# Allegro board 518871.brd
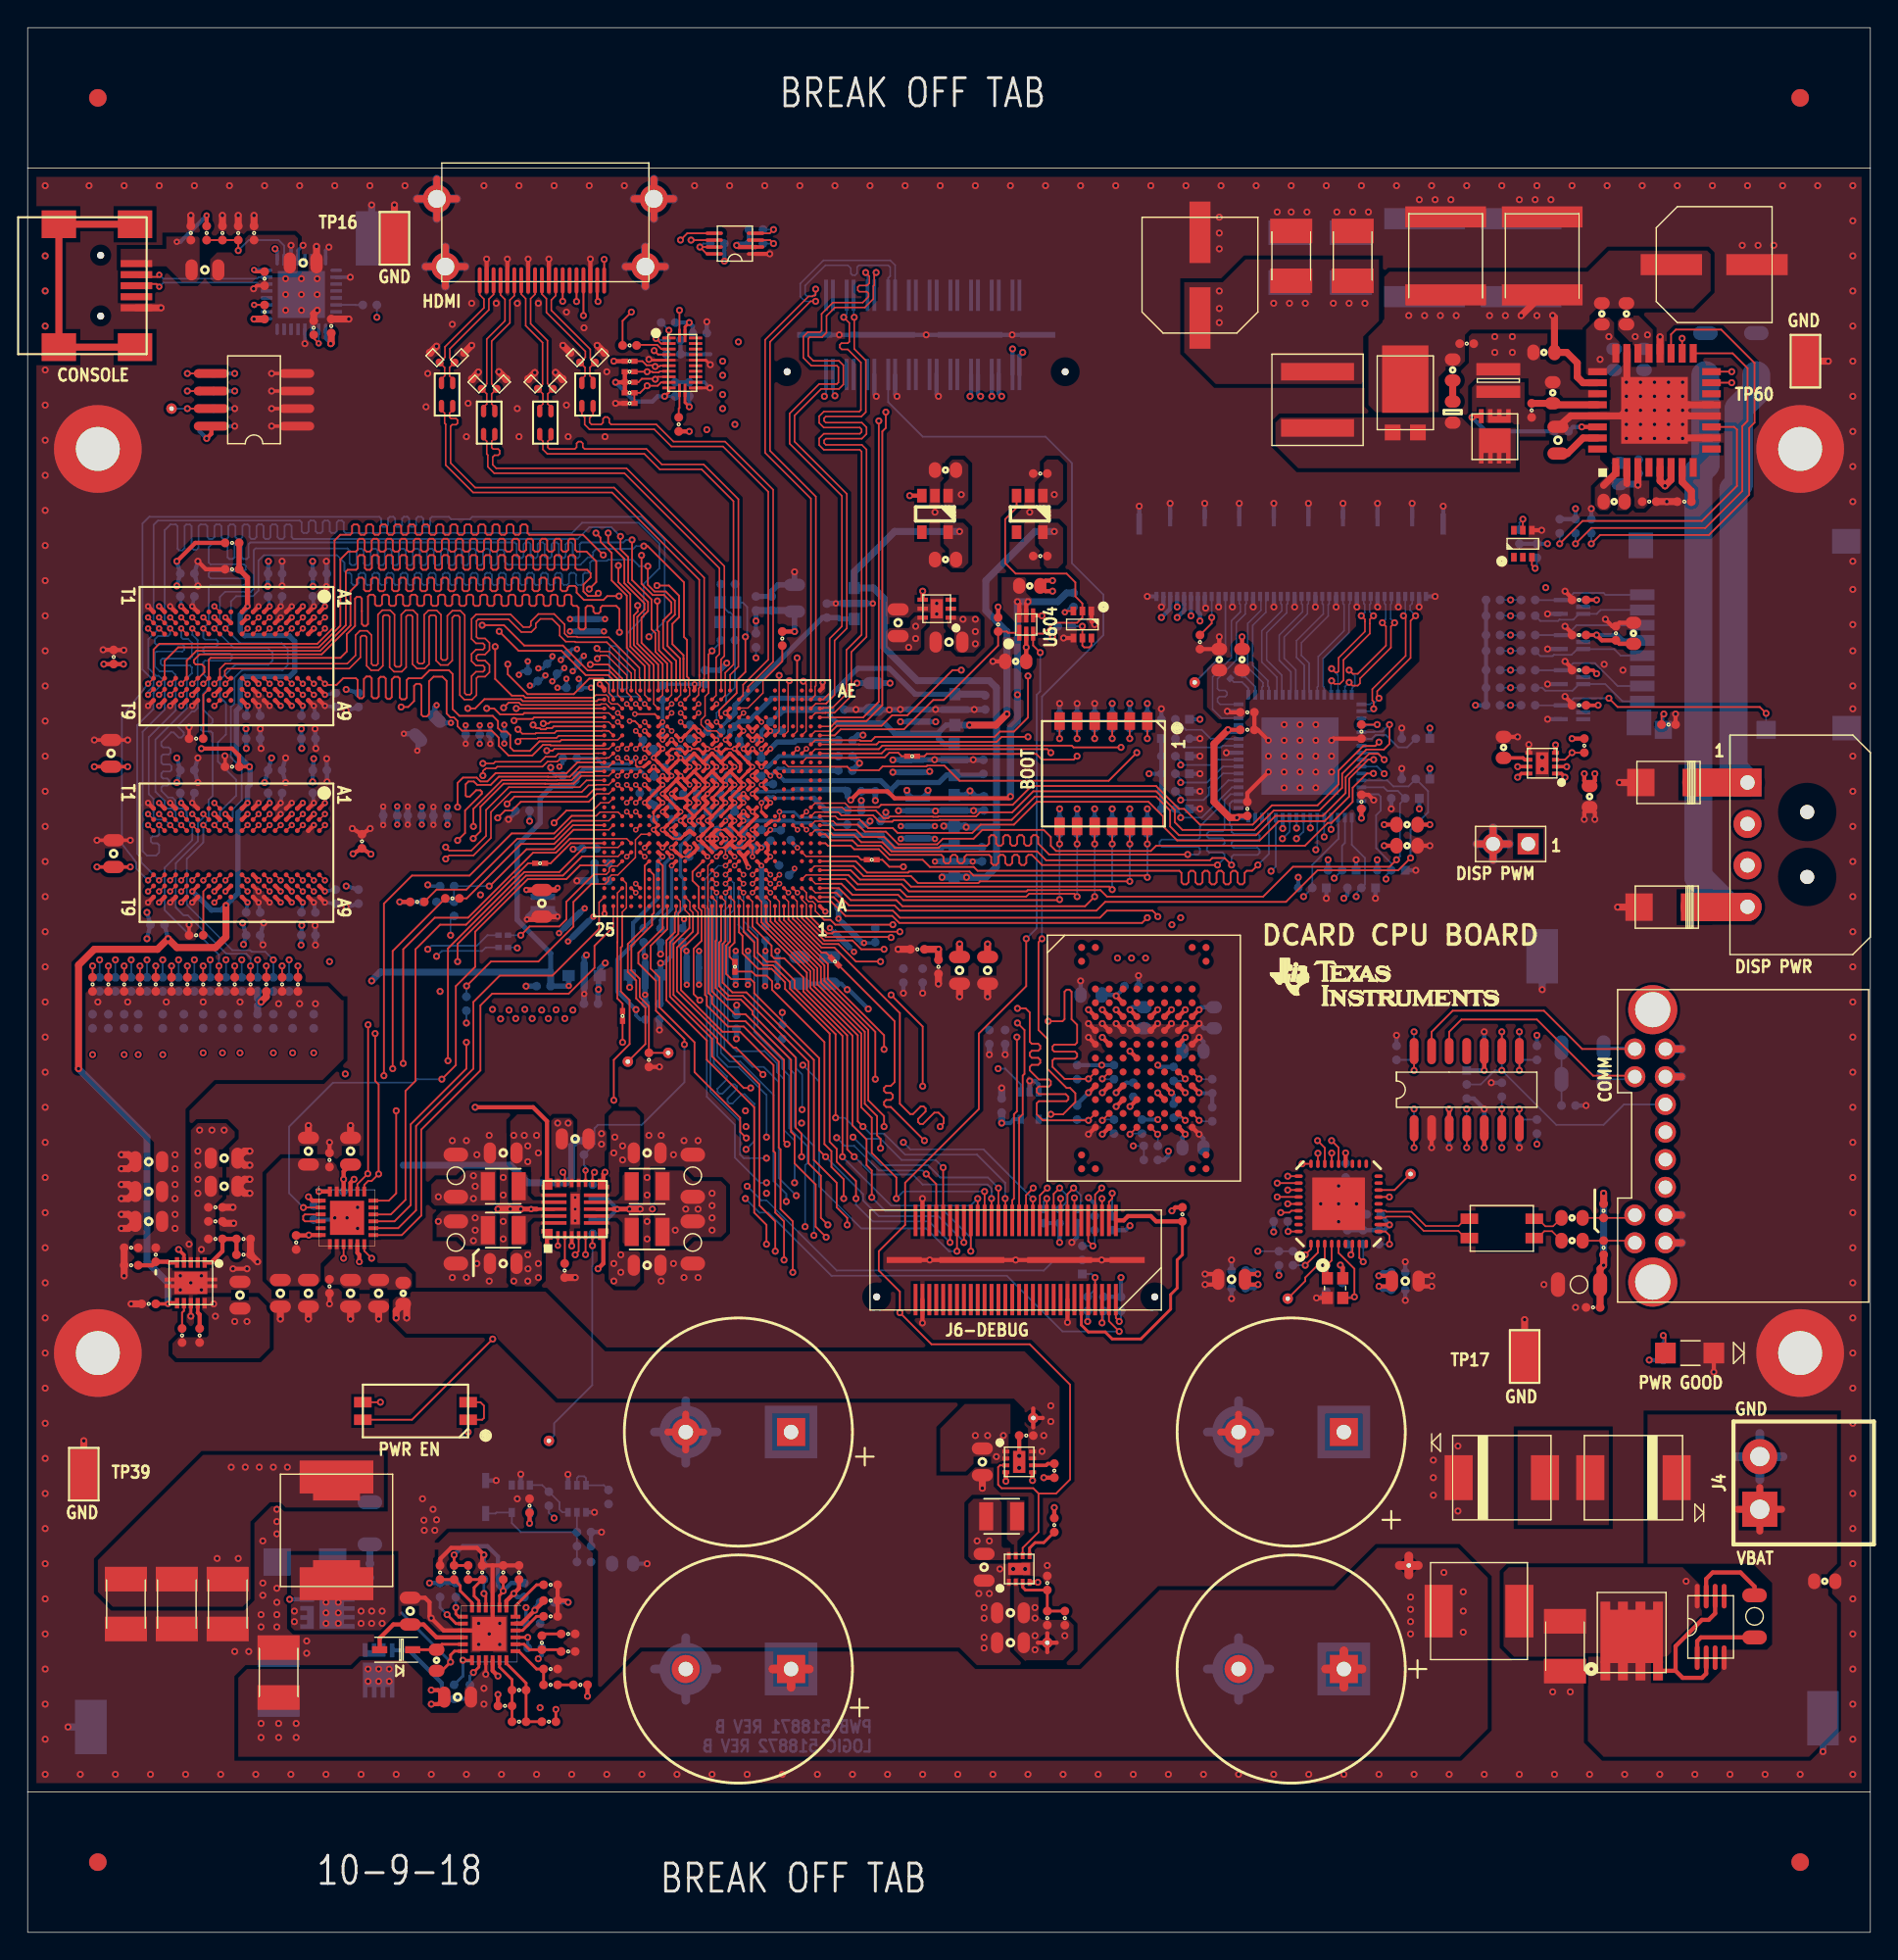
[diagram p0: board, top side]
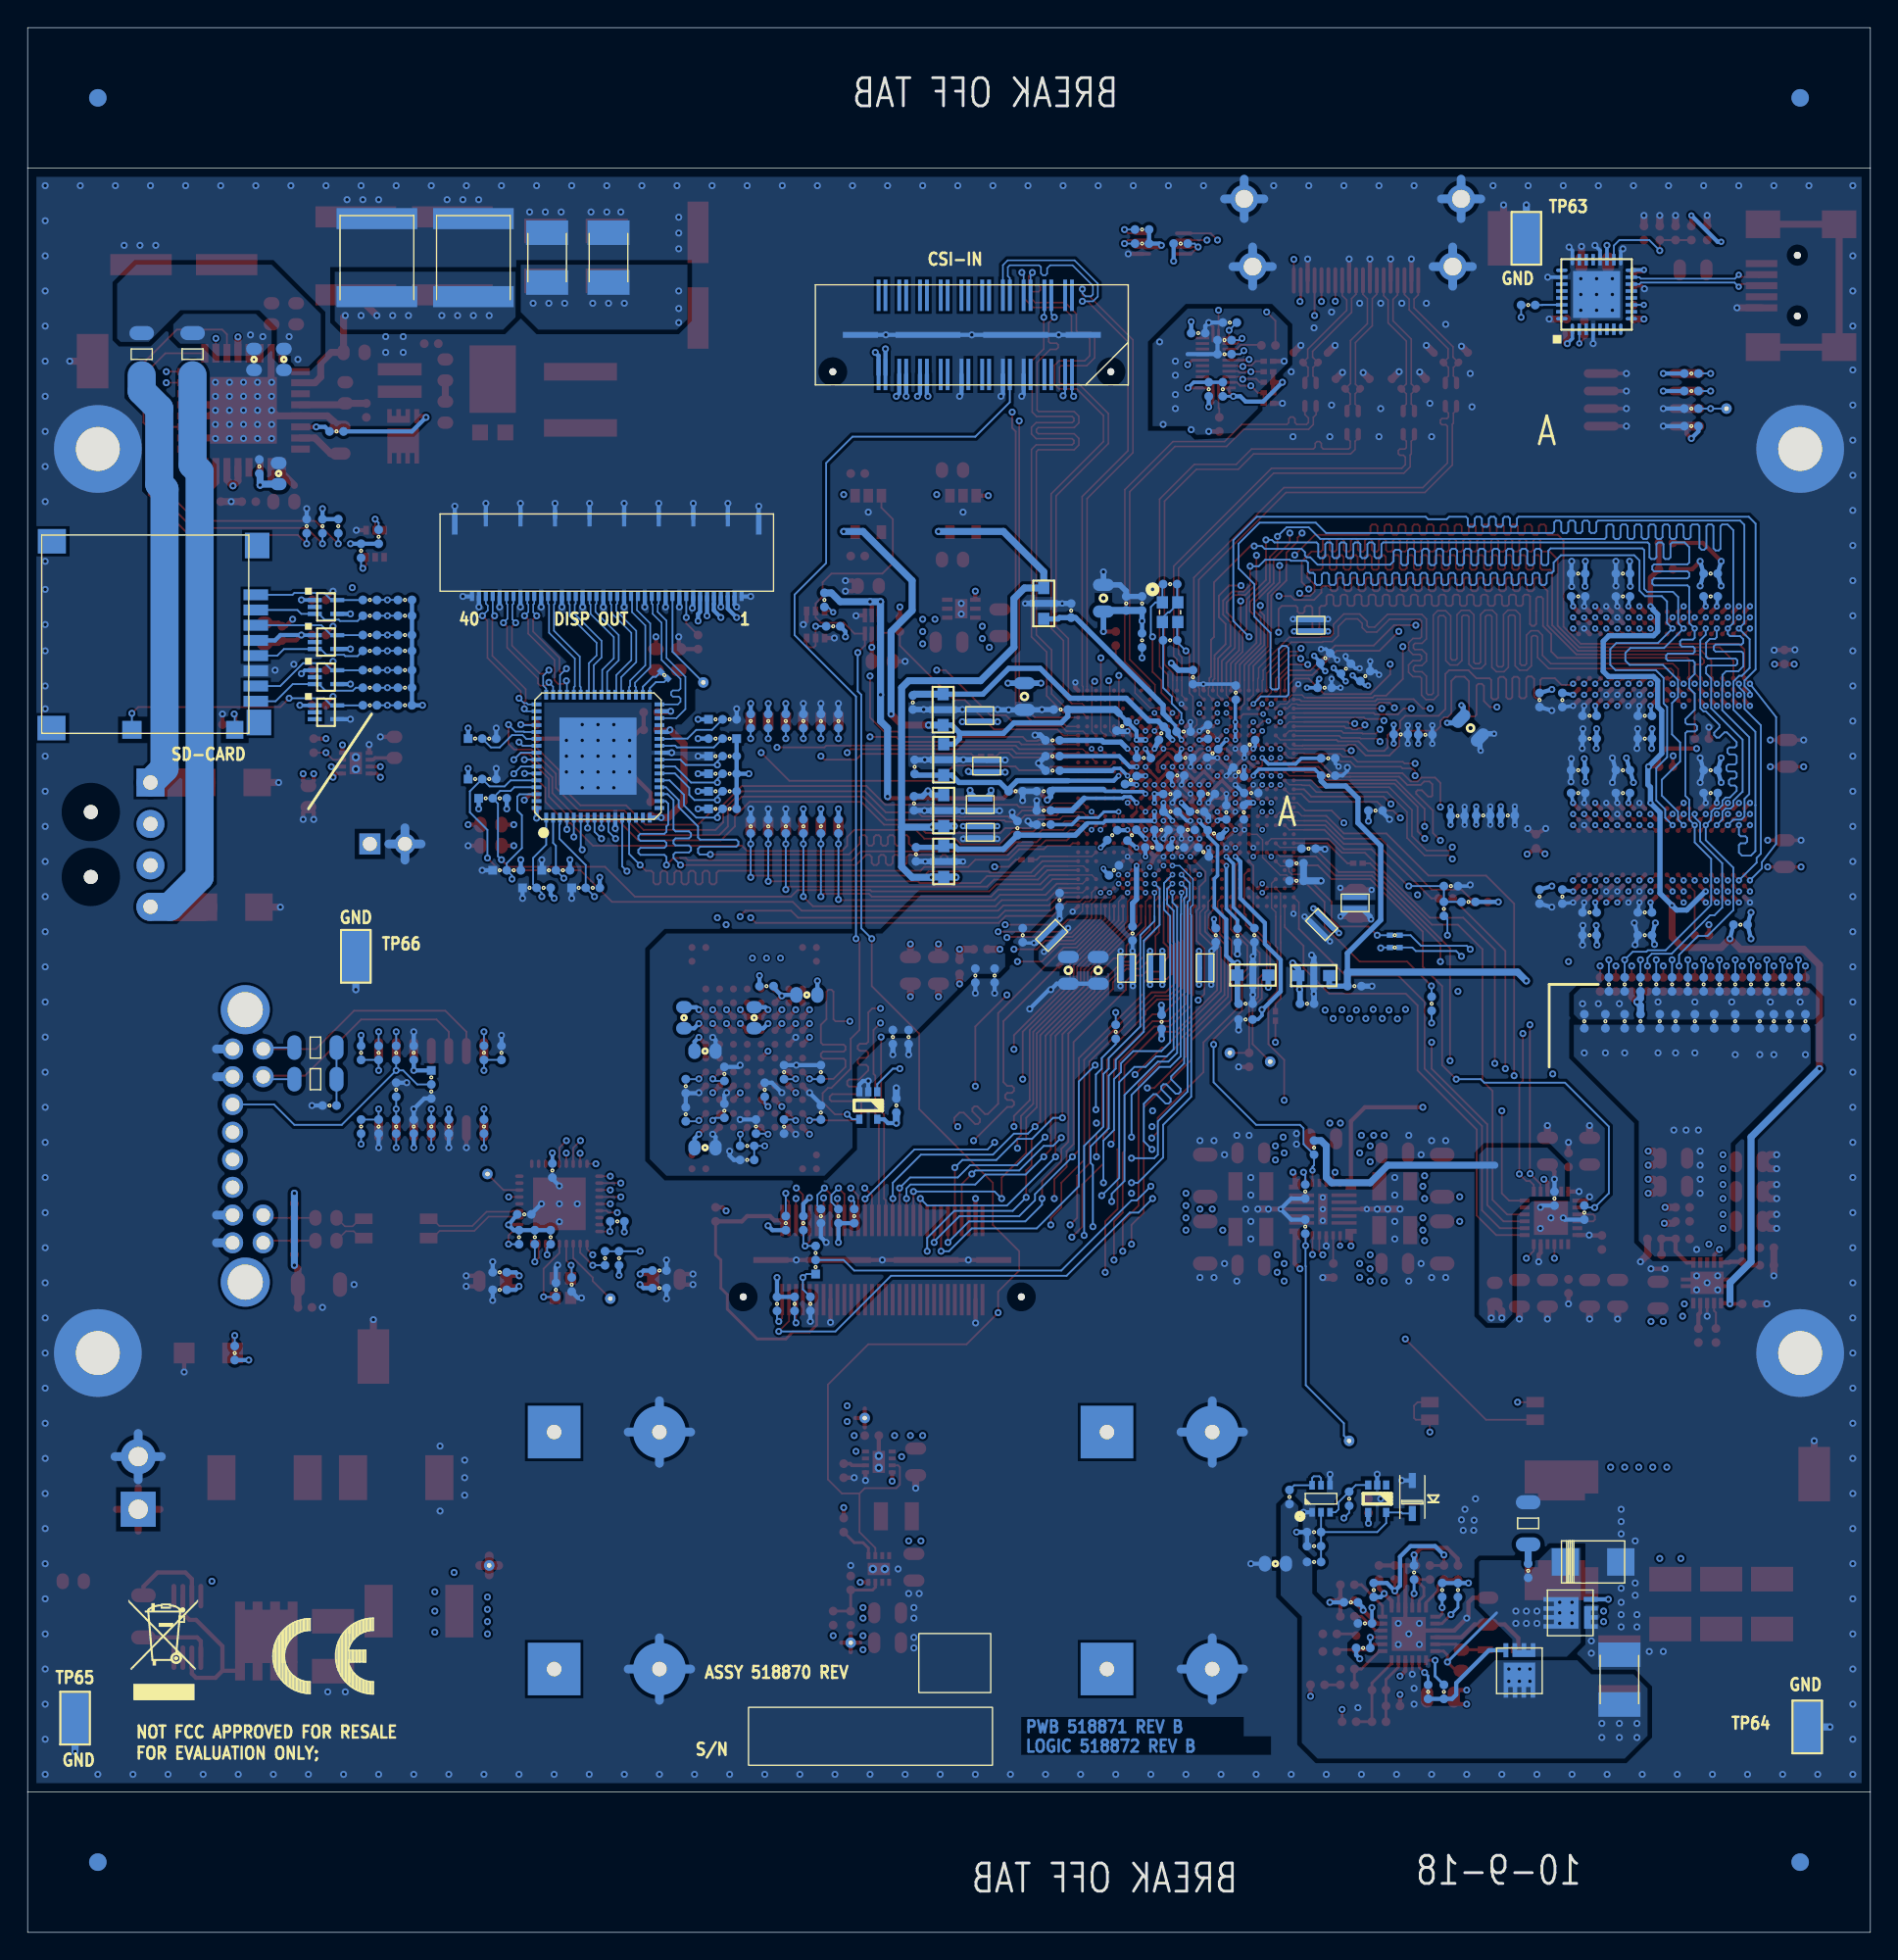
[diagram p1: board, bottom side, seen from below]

Outline 133.35 x 137.79 mm; copper layers: TOP, L2_GND, LY3, LY4, LY5_PWR, BOTTOM. Coordinates in mm from the lower left corner of the outline.
Outline path: 0,127.64 0,137.79 133.35,137.79 133.35,127.64 ; 0,127.64 133.35,127.64 ; 0,127.64 0,10.16 ; 133.35,127.64 133.35,10.16 ; 0,10.16 0,0 133.35,0 133.35,10.16 ; 0,10.16 133.35,10.16

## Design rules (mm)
net group CONN_USB_D: nets CONN_USB_D+ CONN_USB_D-
net group EMAC[1]_TXC: nets EMAC[1]_TXC N3026308320
net group H_MMC1_CLK: nets H_MMC1_CLK N27144522
net group HDMI_TX0+: nets H_HDMI_DY0 HDMI_TX0+
net group HDMI_TX0-: nets H_HDMI_DX0 HDMI_TX0-
net group HDMI_TX1+: nets H_HDMI_DY1 HDMI_TX1+
net group HDMI_TX1-: nets H_HDMI_DX1 HDMI_TX1-
net group HDMI_TX2+: nets H_HDMI_DY2 HDMI_TX2+
net group HDMI_TX2-: nets H_HDMI_DX2 HDMI_TX2-
net group HDMI_TXC+: nets H_HDMI_CLKY HDMI_TXC+
net group HDMI_TXC-: nets H_HDMI_CLKX HDMI_TXC-
net group VOUT3B_CLK: nets N33330487 VOUT3B_CLK
net group CAM: nets H_EMU5 H_EMU8 H_EMU9 H_EMU10 H_EMU11 H_EMU12 H_EMU13 H_EMU14 H_EMU15 H_EMU16 H_EMU17
net group CSI: nets H_CSI2_DX0 H_CSI2_DX1 H_CSI2_DX2 H_CSI2_DY0 H_CSI2_DY1 H_CSI2_DY2
net group DATA_GRP0: nets H_DDR1_D0 H_DDR1_D1 H_DDR1_D2 H_DDR1_D3 H_DDR1_D4 H_DDR1_D5 H_DDR1_D6 H_DDR1_D7 H_DDR1_DQM0 H_DDR1_DQS0_N H_DDR1_DQS0_P
net group DATA_GRP1: nets H_DDR1_D8 H_DDR1_D9 H_DDR1_D10 H_DDR1_D11 H_DDR1_D12 H_DDR1_D13 H_DDR1_D14 H_DDR1_D15 H_DDR1_DQM1 H_DDR1_DQS1_N H_DDR1_DQS1_P
net group DATA_GRP2: nets H_DDR1_D16 H_DDR1_D17 H_DDR1_D18 H_DDR1_D19 H_DDR1_D20 H_DDR1_D21 H_DDR1_D22 H_DDR1_D23 H_DDR1_DQM2 H_DDR1_DQS2_N H_DDR1_DQS2_P
net group DATA_GRP3: nets H_DDR1_D24 H_DDR1_D25 H_DDR1_D26 H_DDR1_D27 H_DDR1_D28 H_DDR1_D29 H_DDR1_D30 H_DDR1_D31 H_DDR1_DQM3 H_DDR1_DQS3_N H_DDR1_DQS3_P
net group EMAC[1]_RX: nets EMAC[1]_RXC EMAC[1]_RXCTL EMAC[1]_RXD0 EMAC[1]_RXD1 EMAC[1]_RXD2 EMAC[1]_RXD3
net group EMAC[1]_TX: nets EMAC[1]_TXCTL EMAC[1]_TXD0 EMAC[1]_TXD1 EMAC[1]_TXD2 EMAC[1]_TXD3
net group MMC2_CLK: nets MMC2_CLK N22073312 N32593135
net group PWR_PH: nets GND_EARTH VCAP_VBBLDO_DSP VCAP_VBBLDO_GPU VCAP_VBBLDO_IVA VCAP_VBBLDO_MPU VCAP_VDDRAM_CORE1 VCAP_VDDRAM_CORE3 VCAP_VDDRAM_CORE4 VCAP_VDDRAM_DSP VCAP_VDDRAM_GPU VCAP_VDDRAM_IVA VCAP_VDDRAM_MPU VCC_LM5141 VDA_HDMI_FIL1V8 VDA_MPU_ABE_FIL1V8 VDA_OSC_FIL1V8 VDDA_LM5141 VDDI_MMC2 VDDR_VREFSTL VHDMI_5V0 VTT_DDR
net group RX: nets RXEIN0+ RXEIN0- RXEIN1+ RXEIN1- RXEIN2+ RXEIN2- RXEIN3+ RXEIN3- RXOCLKIN+ RXOCLKIN- RXOIN0+ RXOIN0- RXOIN1+ RXOIN1- RXOIN2+ RXOIN2- RXOIN3+ RXOIN3-
net group TRD1_N: nets N30512862 TRD1_N TRD_N
net group TRD1_P: nets N30512853 TRD1_P TRD_P
net group VOUT3B: nets VOUT3B_D0 VOUT3B_D1 VOUT3B_D2 VOUT3B_D3 VOUT3B_D4 VOUT3B_D5 VOUT3B_D6 VOUT3B_D7 VOUT3B_D8 VOUT3B_D9 VOUT3B_D10 VOUT3B_D11 VOUT3B_D12 VOUT3B_D13 VOUT3B_D14 VOUT3B_D15 VOUT3B_D16 VOUT3B_D17 VOUT3B_D18 VOUT3B_D19 VOUT3B_D20 VOUT3B_D21 VOUT3B_D22 VOUT3B_D23 VOUT3B_DE VOUT3B_HSYNC VOUT3B_VSYNC

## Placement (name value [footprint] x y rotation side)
C1  NP-2200uF  [CAP300X630UP]  87.63 36.2 180 top
C2  NP-2200uF  [CAP300X630UP]  47.62 36.2 180 top
C3  NP-2200uF  [CAP300X630UP]  47.62 19.05 180 top
C8  10uF  [C1210-70X102]  111.25 20.7 270 top
C23  NP-2200uF  [CAP300X630UP]  87.63 19.05 180 top
C24  0.22uF  [C603-35X45]  130.05 25.4 0 top
C29  1uF  [C805-35X60]  31.11 17.02 180 top
C30  2.2uF 50V X7R  [C1206-40X70]  124.97 22.86 90 top
C36  0.1uF  [C402-25]  35.56 17.53 0 top
C37  10uF  [C1210-70X102]  18.16 18.29 90 bottom
C38  10uF  [C1210-70X102]  18.16 18.8 90 top
C39  0.1uF  [C603-35X45]  29.59 19.68 90 top
C40  150pF  [C402-25]  39.12 20.32 0 top
C41  0.015uF  [C402-25]  39.12 21.59 180 top
C43  0.047uF  [C402-25]  37.85 22.86 180 top
C45  4.7uF  [C805-35X60]  27.69 23.24 90 top
C48  0.01uF  [C402-25]  37.85 24 180 top
C51  0.01uF  [C402-25]  37.85 25.15 180 top
C53  0.1uF  [C402-25]  34.42 26.04 90 top
C54  0.01uF  [C402-25]  32.89 26.04 270 top
C56  22uF  [C1210-70X102]  14.48 23.75 270 top
C59  22uF  [C1210-70X102]  10.79 23.75 270 top
C64  22uF  [C1210-70X102]  7.11 23.75 270 top
C71  0.1uF  [C402-25RD]  11.81 122.94 90 top
C72  4700pF  [C402-25RD]  14.1 122.94 90 top
C73  0.1uF  [C402-25RD]  16.38 122.94 90 top
C78  4.7uF  [C805-35X60]  19.94 120.78 0 top
C80  0.47uF  [SM-7351-CAP-0402]  14.8 100.52 180 top
C81  0.1uF  [C402-25RD]  17.14 119.63 270 top
C82  0.47uF  [SM-7351-CAP-0402]  14.8 98.62 180 top
C83  0.1uF  [C402-25RD]  21.97 116.2 90 top
C84  0.47uF  [SM-7351-CAP-0402]  6.22 92.27 90 top
C89  10uF  [C805-35X60]  6.03 85.29 90 top
C91  0.47uF  [SM-7351-CAP-0402]  14.8 84.33 180 top
C96  0.47uF  [SM-7351-CAP-0402]  24.19 78.93 90 top
C98  10uF  [C805-35X60]  6.22 78.04 90 top
C108  10uF  [C805-35X60]  37.21 74.45 270 top
C114  0.47uF  [SM-7351-CAP-0402]  64.39 71.12 180 top
C118  1uF  [SM-7351-CAP-0402]  65.91 69.85 270 top
C119  4.7uF  [C805-35X60]  67.44 69.6 270 top
C120  10uF  [C805-35X60]  69.47 69.6 270 top
C122  4.7uF  [C603-35X45]  86.23 92.08 90 top
C129  4.7uF  [C603-35X45]  99.82 78.61 0 top
C143  10uF  [C805-35X60]  14.22 56.01 180 top
C144  10uF  [C805-35X60]  8.76 55.75 0 top
C153  10uF  [C805-35X60]  14.22 53.98 180 top
C154  10uF  [C805-35X60]  8.76 53.59 0 top
C155  0.1uF  [SM-7351-CAP-0402]  13.59 52.45 180 top
C156  10uF  [C805-35X60]  8.76 51.44 0 top
C157  1000pF  [C402-25]  13.59 51.44 180 top
C158  0.1uF  [SM-7351-CAP-0402]  7.49 49.53 0 top
C160  1000pF  [C402-25]  15.62 49.02 180 top
C161  10pF  [C402-25]  7.49 48.26 0 top
C163  10uF  [C805-35X60]  15.37 46.1 270 top
C164  0.1uF  [SM-7351-CAP-0402]  8.76 45.47 0 top
C189  10uF  [C805-35X60]  87.12 47.24 180 top
C194  10uF  [C805-35X60]  69.22 26.42 270 top
C203  10uF  [C805-35X60]  71.12 20.95 180 top
C204  10uF  [C805-35X60]  71.12 23.11 180 top
C212  10uF  [C805-35X60]  99.69 47.12 0 top
C220  100pF  [C402-25]  75.06 22.73 90 top
C232  0.1uF  [C603-35X45]  111.76 50.04 180 top
C233  0.1uF  [C603-35X45]  111.76 51.69 180 top
C267  0.1uF  [C402-25]  48.64 115.7 0 bottom
C268  0.1uF  [C402-25]  47.88 111.63 90 bottom
C269  0.1uF  [C402-25]  46.86 111.63 90 bottom
C270  1000pF  [C402-25]  24.77 26.16 270 bottom
C272  0.47uF  [SM-7351-CAP-0402]  21.15 98.3 0 bottom
C273  0.47uF  [SM-7351-CAP-0402]  17.91 98.3 0 bottom
C274  0.47uF  [SM-7351-CAP-0402]  11.56 98.3 0 bottom
C275  0.1uF  [C402-25]  12.95 108.97 180 bottom
C276  10pF  [C402-25]  50.67 97.54 180 bottom
C277  0.1uF  [SM-7351-CAP-0402]  41.53 76.07 180 bottom
C278  0.1uF  [SM-7351-CAP-0402]  21.15 96.65 180 bottom
C279  0.1uF  [SM-7351-CAP-0402]  17.91 96.65 0 bottom
C280  0.1uF  [SM-7351-CAP-0402]  11.56 96.65 0 bottom
C281  10uF  [C805-35X60]  55.5 96.52 90 bottom
C282  0.1uF  [SM-7351-CAP-0402]  35.81 81.15 180 bottom
C283  0.1uF  [SM-7351-CAP-0402]  54.86 79.38 315 bottom
C284  1uF  [SM-7351-CAP-0402]  53.85 96.14 90 bottom
C285  0.1uF  [SM-7351-CAP-0402]  52.7 96.14 90 bottom
C286  1uF  [SM-7351-CAP-0402]  57.84 95.62 90 bottom
C287  0.1uF  [SM-7351-CAP-0402]  41.53 77.34 180 bottom
C288  0.1uF  [SM-7351-CAP-0402]  54.74 76.83 315 bottom
C289  1uF  [SM-7351-CAP-0508]  40.49 94.56 90 bottom
C292  10pF  [C402-25]  50.67 93.47 0 bottom
C293  0.47uF  [SM-7351-CAP-0402]  39.45 92.18 135 bottom
C294  0.47uF  [SM-7351-CAP-0402]  37.95 91.41 135 bottom
C295  0.47uF  [SM-7351-CAP-0402]  36.55 90.88 135 bottom
C296  0.1uF  [SM-7351-CAP-0402]  49.02 90.81 270 bottom
C297  0.47uF  [SM-7351-CAP-0402]  39.5 90.04 180 bottom
C298  0.1uF  [SM-7351-CAP-0402]  45.92 89.69 90 bottom
C299  0.47uF  [SM-7351-CAP-0402]  23.94 89.15 270 bottom
C300  0.1uF  [SM-7351-CAP-0402]  22.29 89.15 270 bottom
C301  1uF  [SM-7351-CAP-0402]  69.29 88.98 270.1 bottom
C302  1uF  [SM-7351-CAP-0402]  58.59 88.46 0 bottom
C303  1uF  [SM-7351-CAP-0508]  64.46 88.03 90 bottom
C304  0.1uF  [SM-7351-CAP-0402]  20.32 88.01 0 bottom
C305  0.1uF  [SM-7351-CAP-0402]  16.32 88.01 0 bottom
C306  0.1uF  [SM-7351-CAP-0402]  54.15 87.26 321.4 bottom
C307  10uF  [C805-35X60]  28.93 87.12 225 bottom
C308  0.1uF  [SM-7351-CAP-0402]  47.93 86.85 90 bottom
C309  0.1uF  [SM-7351-CAP-0402]  49.7 86.87 180 bottom
C310  0.1uF  [SM-7351-CAP-0402]  51.31 86.74 290.4 bottom
C311  0.47uF  [SM-7351-CAP-0402]  33.99 86.66 180 bottom
C312  0.47uF  [SM-7351-CAP-0402]  32.21 86.64 180 bottom
C313  0.47uF  [SM-7351-CAP-0402]  20.32 86.36 0 bottom
C314  0.47uF  [SM-7351-CAP-0402]  16.32 86.36 0 bottom
C315  0.47uF  [SM-7351-CAP-0402]  44.91 85.93 320 bottom
C318  0.1uF  [SM-7351-CAP-0402]  52.58 84.96 181.1 bottom
C319  0.47uF  [SM-7351-CAP-0402]  47.6 85.29 322.7 bottom
C320  1uF  [SM-7351-CAP-0402]  59.18 86.23 360 bottom
C321  0.47uF  [SM-7351-CAP-0402]  49.58 84.96 180 bottom
C322  1uF  [SM-7351-CAP-0402]  39.24 84.94 180 bottom
C323  1uF  [SM-7351-CAP-0508]  63.95 84.37 90 bottom
C324  1uF  [SM-7351-CAP-0402]  69.16 84.32 90 bottom
C325  0.47uF  [SM-7351-CAP-0402]  45.72 83.95 40 bottom
C326  0.47uF  [SM-7351-CAP-0402]  21.15 84.07 0 bottom
C327  0.47uF  [SM-7351-CAP-0402]  17.91 84.07 0 bottom
C328  0.47uF  [SM-7351-CAP-0402]  11.56 84.07 0 bottom
C329  1uF  [SM-7351-CAP-0402]  59.17 84.05 0 bottom
C331  0.1uF  [SM-7351-CAP-0402]  39.23 83.68 180 bottom
C332  0.47uF  [SM-7351-CAP-0402]  50.16 83.69 180 bottom
C333  0.1uF  [SM-7351-CAP-0402]  61.85 82.55 180 bottom
C334  1uF  [SM-7351-CAP-0402]  59.82 81.16 0 bottom
C335  0.1uF  [SM-7351-CAP-0402]  44.81 82.42 0 bottom
C336  0.1uF  [SM-7351-CAP-0402]  21.15 82.42 180 bottom
C337  0.1uF  [SM-7351-CAP-0402]  17.91 82.42 0 bottom
C338  0.1uF  [SM-7351-CAP-0402]  11.56 82.42 0 bottom
C340  0.1uF  [SM-7351-CAP-0402]  50.66 82.35 180 bottom
C341  0.47uF  [SM-7351-CAP-0402]  47.94 82.36 180 bottom
C342  0.1uF  [SM-7351-CAP-0402]  53.52 83.36 145 bottom
C343  1uF  [SM-7351-CAP-0402]  69.2 81.68 270 bottom
C344  1uF  [SM-7351-CAP-0508]  64.42 81.59 270 bottom
C345  0.1uF  [SM-7351-CAP-0402]  59.82 82.55 0 bottom
C347  0.47uF  [SM-7351-CAP-0402]  50.65 81.08 180 bottom
C348  0.47uF  [SM-7351-CAP-0402]  48.72 81.08 180 bottom
C349  0.1uF  [SM-7351-CAP-0402]  46.61 81.03 90 bottom
C351  0.47uF  [SM-7351-CAP-0402]  28.02 80.8 180 bottom
C352  0.47uF  [SM-7351-CAP-0402]  26.24 80.8 180 bottom
C354  0.47uF  [SM-7351-CAP-0402]  29.87 80.77 180 bottom
C356  0.1uF  [SM-7351-CAP-0402]  45.34 81.03 90 bottom
C357  0.47uF  [SM-7351-CAP-0402]  53.44 79.38 309.4 bottom
C358  1uF  [SM-7351-CAP-0402]  59.82 80.14 0 bottom
C359  0.1uF  [SM-7351-CAP-0402]  61.72 79.88 90 bottom
C361  0.1uF  [SM-7351-CAP-0402]  49.4 79.76 180 bottom
C362  0.1uF  [SM-7351-CAP-0402]  51.31 79.76 0 bottom
C364  0.47uF  [SM-7351-CAP-0402]  47.5 79.5 206.5 bottom
C367  0.47uF  [SM-7351-CAP-0402]  50.16 78.49 0 bottom
C368  0.47uF  [SM-7351-CAP-0402]  48.26 78.16 220 bottom
C369  0.1uF  [SM-7351-CAP-0402]  40.65 78.4 180 bottom
C370  0.47uF  [SM-7351-CAP-0402]  51.97 78.49 180 bottom
C372  1uF  [SM-7351-CAP-0402]  69.06 77.99 270 bottom
C373  1uF  [SM-7351-CAP-0508]  64.41 79.59 270 bottom
C374  1uF  [SM-7351-CAP-0402]  44.58 72.14 270 bottom
C375  1000pF  [C402-25]  30.35 75.69 0 bottom
C377  0.47uF  [SM-7351-CAP-0402]  23.94 74.93 270 bottom
C378  0.1uF  [SM-7351-CAP-0402]  22.29 74.93 270 bottom
C379  0.1uF  [SM-7351-CAP-0402]  58.67 74.68 270 bottom
C380  1uF  [SM-7351-CAP-0508]  37.29 74.47 270 bottom
C382  0.1uF  [SM-7351-CAP-0402]  20.32 73.79 0 bottom
C383  0.1uF  [SM-7351-CAP-0402]  16.32 73.79 0 bottom
C385  1uF  [SM-7351-CAP-0508]  39.72 72.91 315 bottom
C386  0.47uF  [SM-7351-CAP-0402]  9.4 72.9 180 bottom
C388  1uF  [SM-7351-CAP-0402]  53.39 72.26 270 bottom
C390  0.1uF  [SM-7351-CAP-0402]  61.34 72.14 270 bottom
C391  0.47uF  [SM-7351-CAP-0402]  20.32 72.14 0 bottom
C392  0.47uF  [SM-7351-CAP-0402]  16.32 72.14 0 bottom
C393  1uF  [SM-7351-CAP-0508]  59.24 72.12 45 bottom
C394  1uF  [SM-7351-CAP-0402]  45.8 72.11 270 bottom
C395  1uF  [SM-7351-CAP-0402]  47.37 72.14 270 bottom
C401  1uF  [SM-7351-CAP-0508]  48.14 69.78 180 bottom
C402  1uF  [SM-7351-CAP-0508]  51.68 69.77 180 bottom
C403  1uF  [SM-7351-CAP-0508]  53.82 69.75 180 bottom
C406  1uF  [SM-7351-CAP-0402]  37.34 68.45 180 bottom
C407  1uF  [SM-7351-CAP-0402]  40.77 67.18 180 bottom
C408  1uF  [SM-7351-CAP-0402]  45.21 67.18 180 bottom
C409  0.1uF  [C402-25]  96.52 81.79 90 top
C410  0.1uF  [C402-25]  88.27 81.28 90 top
C411  0.22uF  [C603-35X45]  84.33 63.75 0 bottom
C412  1uF  [SM-7351-CAP-0402]  45.21 66.04 0 bottom
C413  0.47uF  [SM-7351-CAP-0402]  20.7 65.91 270 bottom
C414  0.47uF  [SM-7351-CAP-0402]  19.18 65.91 270 bottom
C415  0.47uF  [SM-7351-CAP-0402]  17.78 65.91 270 bottom
C416  0.1uF  [SM-7351-CAP-0402]  16.64 65.91 270 bottom
C417  0.47uF  [SM-7351-CAP-0402]  15.24 65.91 270 bottom
C418  0.47uF  [SM-7351-CAP-0402]  14.1 65.91 270 bottom
C419  0.47uF  [SM-7351-CAP-0402]  12.7 65.91 270 bottom
C420  0.47uF  [SM-7351-CAP-0402]  11.3 65.91 270 bottom
C421  0.47uF  [SM-7351-CAP-0402]  9.78 65.91 270 bottom
C422  0.47uF  [SM-7351-CAP-0402]  8 65.91 270 bottom
C423  0.47uF  [SM-7351-CAP-0402]  6.99 65.91 270 bottom
C424  0.47uF  [SM-7351-CAP-0402]  5.84 65.91 270 bottom
C425  0.47uF  [SM-7351-CAP-0402]  4.7 65.91 270 bottom
C426  1uF  [SM-7351-CAP-0402]  51.29 65.87 270 bottom
C427  2.2uF  [C603-35X45]  84.33 56.77 0 bottom
C428  0.47uF  [SM-7351-CAP-0402]  63.37 69.22 270 bottom
C429  0.1uF  [C402-25]  88.27 88.27 0 top
C430  0.1uF  [SM-7351-CAP-0402]  70.74 64.77 270 bottom
C431  0.1uF  [SM-7351-CAP-0402]  69.6 64.77 270 bottom
C432  0.1uF  [SM-7351-CAP-0402]  59.18 85.09 0 bottom
C433  0.1uF  [C402-25]  79.88 68.45 0 bottom
C434  1uF  [SM-7351-CAP-0402]  64.77 69.22 270 bottom
C435  4.7uF  [C603-35X45]  80.77 66.17 270 bottom
C436  2.2uF  [C603-35X45]  76.96 67.82 180 bottom
C437  0.22uF  [C603-35X45]  85.85 66.17 270 bottom
C442  0.1uF  [C402-25]  70.48 59.82 270 bottom
C503  10pF  [C402-25]  93.98 46.86 270 bottom
C506  10pF  [C402-25]  95.12 46.48 90 bottom
C507  100nF  [C402-25]  95.38 55.12 270 bottom
C508  1uF  [C402-25]  87.63 46.61 180 bottom
C509  10nF  [C402-25]  87.63 47.88 180 bottom
C511  100nF  [C402-25]  97.41 51.94 180 bottom
C514  0.1uF  [C402-25]  102.87 58.29 270 bottom
C518  1uF  [C402-25]  99.19 47.75 0 bottom
C519  10nF  [C402-25]  99.19 46.48 0 bottom
C521  0.1uF  [C402-25]  105.41 58.29 90 bottom
C525  4700pF  [C402-25]  111.51 59.82 0 bottom
C536  10uF  [C805-35X60]  58.04 69.6 270 bottom
C537  10uF  [C805-35X60]  55.88 69.6 270 bottom
C540  0.1uF  [C402-25]  114.94 93.98 90 top
C541  10uF  [C603-35X45]  116.2 93.98 90 top
C542  0.1uF  [C402-25]  112.27 96.39 180 top
C543  0.1uF  [C402-25]  112.27 88.77 180 top
C544  0.1uF  [C402-25]  112.27 91.31 180 top
C545  0.1uF  [C402-25]  112.27 93.85 180 top
C546  10uF  [C603-35X45]  113.03 82.17 270 top
C547  NP  [C603-35X45]  106.81 85.72 90 top
C551  10uF  [C805-35X60]  61.21 89.41 270 bottom
C552  0.22uF  [C603-35X45]  43.05 26.67 0 bottom
C553  150pF  [C402-25]  40.26 27.94 0 bottom
C554  NP-0.1uF  [C402-25]  36.32 30.86 270 top
C556  10uF  [C805-35X60]  23.37 56.52 90 top
C557  0.1uF  [C402-25]  22.86 53.09 270 bottom
C558  10uF  [C805-35X60]  20.32 56.52 90 top
C559  10uF  [C805-35X60]  18.29 46.23 270 top
C560  10uF  [C805-35X60]  20.32 46.23 270 top
C561  0.1uF  [C402-25]  21.84 55.88 90 top
C562  0.1uF  [C402-25]  21.84 46.74 270 top
C563  10uF  [C805-35X60]  25.4 46.23 270 top
C565  10uF  [C805-35X60]  23.37 46.23 270 top
C566  0.1uF  [C402-25]  105.41 63.63 90 bottom
C567  0.1uF  [C402-25]  19.43 49.91 90 top
C568  0.1uF  [C402-25]  88.27 87 0 top
C569  4.7nF  [C1206-40X70]  112.27 46.86 0 top
C600  4.7uF  [C805-35X60]  62.99 94.74 270 top
C601  22uF  [C1206-40X70]  30.99 54.74 90 top
C602  22uF  [C1206-40X70]  30.99 49.91 270 top
C603  4.7uF  [C805-35X60]  66.67 93.34 0 top
C604  0.1uF  [C402-25RD]  72.26 35.94 180 top
C605  10uF  [C805-35X60]  34.42 48.39 180 top
C606  10uF  [C805-35X60]  34.42 56.39 180 top
C607  4.7uF  [C805-35X60]  69.09 34.04 270 top
C608  NP-1000pF  [C402-25]  74.3 33.4 270 top
C609  2.2uF  [C603-35X45]  66.42 99.31 180 top
C610  10uF  [C805-35X60]  39.62 57.4 0 top
C611  2.2uF  [C603-35X45]  72.52 97.41 180 top
C612  10uF  [C805-35X60]  44.83 48.26 0 top
C613  10uF  [C805-35X60]  44.83 56.39 0 top
C614  2.2uF  [C603-35X45]  66.42 105.79 180 top
C615  22uF  [C1206-40X70]  48.13 49.91 270 top
C616  22uF  [C1206-40X70]  48.13 54.74 90 top
C617  2.2uF  [C603-35X45]  71.5 91.95 0 top
C618  0.1uF  [C402-25RD]  73.28 99.57 180 top
C619  1uF  [C402-25]  73.28 105.54 180 top
C620  10uF  [C1210-70X102]  91.44 121.28 90 top
C621  10uF  [C1210-70X102]  95.89 121.28 90 top
C622  10uF  [C1210-70X102]  95.76 121.16 90 bottom
C623  10uF  [C1210-70X102]  91.31 121.16 90 bottom
C624  33uF  [CAP-F-8383A]  84.84 119.89 180 top
C625  10uF  [C2220-60X230]  108.08 121.16 90 bottom
C626  10uF  [C2220-60X230]  101.09 121.16 90 bottom
C627  10uF  [C2220-60X230]  102.62 121.28 90 top
C628  10uF  [C2220-60X230]  109.6 121.28 90 top
C629  33uF  [CAP-F-8383A]  122.05 120.65 90 top
C630  1uF  [C603-35X45]  114.81 103.5 0 top
C631  1000pF  [C603-35X45]  110.36 111.38 270 top
C632  1uF  [C603-35X45]  115.19 105.54 270 bottom
C633  0.01uF  [C402-25]  117.35 103.5 180 top
C634  10uF  [C805-35X60]  110.74 107.95 270 top
C635  33pF  [C603-35X45]  109.73 114.3 0 top
C636  220pF  [C603-35X45]  103.12 113.03 270 top
C637  220pF  [C603-35X45]  113.92 117.09 270 top
C638  220pF  [C603-35X45]  114.81 113.79 90 bottom
C639  220pF  [C603-35X45]  115.7 117.09 270 top
C640  220pF  [C603-35X45]  116.97 113.79 90 bottom
C641  0.01uF  [C402-25]  116.59 106.05 270 bottom
C642  0.01uF  [C402-25]  104.14 114.94 180 top
D5  PMEG6010CEJ,115  [SOD323]  26.67 20.45 180 top
D21  SMCJ14A-13-F  [SMC-80X128]  106.68 32.89 0 top
D22  SMCJ30A-13-F  [SMC-80X128]  116.2 32.89 180 top
D23  B170-13-F  [SMA2-78SQ]  20.07 26.8 180 bottom
D24  NP-6.2V  [SOD323]  33.15 31.5 90 bottom
D25  PDS5100H-13-01  [DIODE-POWERDI5]  99.69 111.38 90 top
D26  SMAJ48A-13-F  [SMA2-78SQ]  118.75 83.19 180 top
D27  SMAJ48A-13-F  [SMA2-78SQ]  118.62 74.17 180 top
DS1  LED_GRN  [LED1206-59X59]  120.27 41.91 180 top
E1  80dB @ 27MHz  [EMI-NFM21P]  59.82 96.14 270 bottom
E2  80dB @ 27MHz  [EMI-NFM21P]  67.1 88.46 90 bottom
E3  80dB @ 27MHz  [EMI-NFM21P]  67.06 84.84 270 bottom
E4  80dB @ 27MHz  [EMI-NFM21P]  67.06 81.15 90 bottom
E5  80dB @ 27MHz  [EMI-NFM21P]  67.06 77.47 90 bottom
E6  80dB @ 27MHz  [EMI-NFM21P]  44.68 69.26 0 bottom
E7  80dB @ 27MHz  [EMI-NFM21P]  40.28 69.22 0 bottom
FL3  DLW21SN900HQ2  [EMI-36X15-DLW21-RDPADS]  30.35 111.25 90 top
FL4  DLW21SN900HQ2  [EMI-36X15-DLW21-RDPADS]  40.51 111.25 90 top
FL7  DLW21SN900HQ2  [EMI-36X15-DLW21-RDPADS]  33.4 109.22 90 top
FL8  DLW21SN900HQ2  [EMI-36X15-DLW21-RDPADS]  37.47 109.22 90 top
J1  NP  [JUMP1X2-6040]  108.58 78.74 270 top
J4  Phoenix - 1803277  [CON2R-150]  125.35 30.61 90 top
J7  USBMINI_AB  [SAMTEC-MUSB]  7.87 119.13 270 top
J14  MIPI-QSH-030  [QSH-030-01-F]  71.5 48.64 180 top
J17  Molex 34826-0124  [MOLEX-34826-0124]  117.6 56.9 90 top
J24  Molex_0436500400  [MOLEX4-043650]  124.46 83.19 90 top
J25  FH41-40S-0.5SH_5  [FH41-40S-SH]  91.44 99.69 0 bottom
L1  3.3uH, 5A  [IND2-7030D]  105.03 23.24 180 top
L6  2.2uH  [IND-IHLP-COMBO]  22.35 29.08 90 top
L9  BLM21PG221SN1  [L805-35X60]  12.83 120.27 0 top
L16  BLM18AG221SN1D  [L603-35X45]  99.82 80.14 0 top
L17  BLM18AG221SN1D  [L603-35X45]  87.88 92.08 90 top
L34  DFE252012PD-2R2M  [IND2520-40X80]  70.48 30.1 0 top
L44  AE2002  [CHOKE4-AE2002]  106.68 50.93 180 top
L45  BLM18AG221SN1D  [L603-35X45]  27.18 46.23 270 top
L600  0.47uH  [IND2520-40X80]  34.42 50.8 0 top
L601  0.47uH  [IND2520-40X80]  34.42 53.98 0 top
L602  0.47uH  [IND2520-40X80]  44.83 50.67 180 top
L603  0.47uH  [IND2520-40X80]  44.83 53.98 180 top
L604  22uH  [COIL-XAL60]  93.34 110.87 270 top
M1  -  [MHP125-250]  128.27 107.31 0 top
M2  -  [MHP125-250]  128.27 41.91 0 top
M3  -  [MHP125-250]  5.08 107.31 0 top
M4  -  [MHP125-250]  5.08 41.91 0 top
NOREF  -  [unnamed]  5.08 132.72 0 top
NOREF#2  -  [#2]  -332.71 -212.42 0 top
NOREF#3  -  [#2]  133.35 10.16 90 top
NOREF#4  -  [#2]  0 137.79 0 top
NOREF#5  -  [#2]  133.35 0 90 top
NOREF#6  -  [unnamed]  128.27 5.08 0 top
NOREF#7  -  [#2]  89.03 66.8 0 top
NOREF#8  -  [#2]  133.35 0 90 top
NOREF#9  -  [#2]  -332.71 -212.42 0 top
NOREF#10  -  [unnamed]  128.27 132.72 0 top
NOREF#11  -  [unnamed]  5.08 5.08 0 top
NOREF#12  -  [unnamed]  128.27 5.08 180 bottom
NOREF#13  -  [unnamed]  128.27 132.72 180 bottom
NOREF#14  -  [#2]  127 16.26 180 bottom
NOREF#15  -  [unnamed]  5.08 5.08 180 bottom
NOREF#16  -  [unnamed]  5.08 132.72 180 bottom
NOREF#17  -  [#2]  112.14 19.94 180 bottom
P1  HDMI-RA-19-TYPEA  [HDMI-SMT-W-FLANGE-RDPADS]  37.47 119.51 180 top
P9  QSH-020-01-L-D-DP-A  [QSH-020-DP-A]  65.02 115.57 0 bottom
P10  Micro SD, Reverse  [MOLEX-502774-0891]  124.21 93.98 270 bottom
Q3  SQJ422EP  [PWR-Q5A-SLPS319]  116.08 18.92 0 top
Q9  BSZ068N06NSATMA1  [TSDSON8]  25.4 18.92 0 bottom
Q10  BSZ068N06NSATMA1  [TSDSON8]  21.72 23.11 90 bottom
Q12  BSS138PS  [SOT363-16X45]  39.75 31.37 180 bottom
Q600  BSS138PS  [SOT363-16X45]  76.33 94.61 180 top
Q602  BSS138PS  [SOT363-16X45]  108.2 100.46 0 top
Q603  BSZ068N06NSATMA1  [TSDSON8]  106.17 108.2 180 top
R18  6.04k  [R402-25]  37.72 15.24 180 top
R22  0  [R402-25]  34.54 16.38 180 top
R23  200  [R402-25]  40.01 17.91 0 top
R24  34.8K  [R402-25]  37.85 17.91 0 top
R25  240  [R402-25]  43.56 114.81 0 top
R26  20K  [R402-25]  37.85 19.05 180 top
R27  NP  [R201-6P6SPC]  43.56 113.67 180 top
R28  NP  [R201-6P6SPC]  43.56 112.9 180 top
R29  3.01K  [R402-25]  37.21 20.95 270 top
R30  NP  [R201-6P6SPC]  43.56 112.14 180 top
R31  NP  [R201-6P6SPC]  43.56 111.38 0 top
R32  NP  [R201-6P6SPC]  43.56 110.62 180 top
R33  10K  [R402-25]  47.12 109.09 90 top
R34  0  [R402-25]  31.88 26.04 90 top
R35  NP  [R402-25]  30.86 26.04 90 top
R36  0  [R402-25]  29.84 26.04 270 top
R39  10K  [R402-25]  35.56 26.04 270 top
R51  4.7K  [R402-25]  12.95 122.94 90 top
R52  10K  [R402-25]  15.24 122.94 90 top
R55  10K  [R402-25]  17.14 117.22 90 top
R56  NP  [R402-25]  20.7 116.08 270 top
R64  240  [R402-25]  12.19 86.36 180 top
R66  100  [R201-6P6SPC]  64.01 85.09 180 top
R70  22  [R402-25]  30.73 74.8 180 top
R71  2.2K  [R402-25]  28.19 74.55 0 top
R75  0  [R201-6P6SPC]  37.08 77.34 180 top
R76  240  [R402-25]  12.19 72.14 180 top
R83  49.9  [SM-7351-RES-0402]  4.7 68.58 90 top
R84  49.9  [SM-7351-RES-0402]  5.84 68.58 90 top
R85  49.9  [SM-7351-RES-0402]  6.99 68.58 90 top
R86  49.9  [SM-7351-RES-0402]  8.13 68.58 90 top
R87  49.9  [SM-7351-RES-0402]  9.27 68.58 90 top
R88  49.9  [SM-7351-RES-0402]  10.41 68.58 90 top
R89  49.9  [SM-7351-RES-0402]  11.56 68.58 90 top
R90  49.9  [SM-7351-RES-0402]  12.7 68.58 90 top
R91  49.9  [SM-7351-RES-0402]  13.84 68.58 90 top
R92  49.9  [SM-7351-RES-0402]  14.99 68.58 90 top
R93  49.9  [SM-7351-RES-0402]  16.13 68.58 90 top
R94  49.9  [SM-7351-RES-0402]  17.27 68.58 90 top
R95  49.9  [SM-7351-RES-0402]  18.41 68.58 90 top
R96  49.9  [SM-7351-RES-0402]  19.56 68.58 90 top
R97  0  [R201-6P6SPC]  43.05 66.29 90 top
R99  0  [R201-6P6SPC]  58.42 70.23 135 top
R101  0  [R201-6P6SPC]  51.18 69.85 90 top
R104  2.2K  [R402-25]  44.96 63.12 90 top
R117  10K  [R402-25]  13.59 50.16 180 top
R118  10K  [R402-25]  15.62 50.16 180 top
R120  10  [R402-25]  9.27 49.02 90 top
R128  10K  [R402-25]  11.18 43.18 270 top
R129  100K  [R402-25]  12.45 43.18 270 top
R140  475K  [R402-25]  73.79 22.73 270 top
R141  150K  [R402-25]  73.79 25.27 270 top
R143  475K  [R402-25]  74.3 29.46 90 top
R152  62  [R1206-40X70]  112.52 61.72 0 bottom
R202  1K  [R402-25]  118.36 41.91 270 bottom
R212  NP  [R402-25]  46.35 116.46 0 bottom
R213  0  [R402-25]  30.86 17.4 90 bottom
R214  0  [R402-25]  32 17.4 270 bottom
R215  NP  [R402-25]  46.74 115.19 0 bottom
R216  10K  [R402-25]  46.74 114.17 180 bottom
R217  100K  [R402-25]  36.7 20.57 0 bottom
R218  10K  [R402-25]  36.58 22.35 0 bottom
R219  0  [R402-25]  29.84 24.77 270 bottom
R220  3.3  [R402-25]  30.99 24.77 90 bottom
R221  10K  [R402-25]  35.94 24.77 90 bottom
R222  42.2K  [R402-25]  33.02 26.04 270 bottom
R225  1.0  [R1206-40X70]  24.77 29.59 90 bottom
R226  NP  [R402-25]  106.05 92.71 0 bottom
R227  47K  [R402-25]  106.05 93.85 0 bottom
R228  47K  [R402-25]  106.05 91.31 0 bottom
R229  47K  [R402-25]  106.05 95.25 0 bottom
R230  47K  [R402-25]  106.05 90.04 0 bottom
R231  47K  [R402-25]  106.05 96.39 0 bottom
R232  22  [R402-25]  24.77 117.73 180 bottom
R233  3.32K  [R402-25]  12.95 112.78 0 bottom
R234  3.32K  [R402-25]  12.95 111.51 0 bottom
R235  10K  [R402-25]  12.95 110.24 0 bottom
R236  NP  [R402-25]  52.7 93.47 90 bottom
R240  1K  [R402-25]  74.68 87.63 270 bottom
R241  10K  [R402-25]  74.68 80.01 90 bottom
R243  10K  [R402-25]  75.95 80.01 90 bottom
R244  1K  [R402-25]  75.95 87.63 270 bottom
R245  2K  [R402-25]  52.7 122.17 0 bottom
R246  2K  [R402-25]  52.7 123.19 0 bottom
R247  10K  [R402-25]  77.22 80.01 90 bottom
R248  1K  [R402-25]  77.22 87.63 270 bottom
R249  4.7k  [R402-25]  49.91 122.17 180 bottom
R250  1K  [R402-25]  78.49 87.63 270 bottom
R251  10K  [R402-25]  78.49 80.01 90 bottom
R254  1K  [R402-25]  79.76 87.63 270 bottom
R255  10K  [R402-25]  79.76 80.01 90 bottom
R258  1K  [R402-25]  81.03 87.63 270 bottom
R259  10K  [R402-25]  81.03 80.01 90 bottom
R262  10K  [R402-25]  29.08 74.55 180 bottom
R263  100  [R402-25]  30.86 74.04 270 bottom
R264  22  [R402-25]  31.75 67.18 270 bottom
R265  0  [R201-6P6SPC]  34.42 72.14 0 bottom
R266  0  [R201-6P6SPC]  34.42 71.25 0 bottom
R268  47K  [R402-25]  85.72 61.21 90 bottom
R269  47K  [R402-25]  78.61 62.23 270 bottom
R270  47K  [R402-25]  85.72 59.18 270 bottom
R271  47K  [R402-25]  75.95 59.31 270 bottom
R272  47K  [R402-25]  82.93 62.1 270 bottom
R273  47K  [R402-25]  75.95 62.23 270 bottom
R276  49.9  [SM-7351-RES-0402]  18.92 68.58 90 bottom
R277  49.9  [SM-7351-RES-0402]  17.78 68.58 90 bottom
R278  49.9  [SM-7351-RES-0402]  16.64 68.58 90 bottom
R279  49.9  [SM-7351-RES-0402]  15.49 68.58 90 bottom
R280  49.9  [SM-7351-RES-0402]  14.35 68.58 90 bottom
R281  49.9  [SM-7351-RES-0402]  13.21 68.58 90 bottom
R282  49.9  [SM-7351-RES-0402]  12.06 68.58 90 bottom
R283  49.9  [SM-7351-RES-0402]  10.92 68.58 90 bottom
R284  49.9  [SM-7351-RES-0402]  9.78 68.58 90 bottom
R285  49.9  [SM-7351-RES-0402]  8.64 68.58 90 bottom
R286  49.9  [SM-7351-RES-0402]  7.49 68.58 90 bottom
R287  49.9  [SM-7351-RES-0402]  6.35 68.58 90 bottom
R288  49.9  [SM-7351-RES-0402]  5.21 68.58 90 bottom
R289  47K  [R402-25]  82.93 59.44 270 bottom
R291  47K  [R402-25]  78.61 58.29 90 bottom
R292  22  [R402-25]  54.61 65.15 270 bottom
R295  47K  [R402-25]  80.64 58.29 270 bottom
R296  1K  [R402-25]  80.01 60.96 90 bottom
R299  0  [R402-25]  81.28 56.9 0 bottom
R300  NP  [R402-25]  81.28 55.88 180 bottom
R307  4.7K  [R402-25]  78.49 51.31 90 bottom
R308  100  [R402-25]  83.57 51.94 270 top
R309  0  [R402-25]  75.95 51.82 90 bottom
R310  4.7K  [R402-25]  74.68 51.82 90 bottom
R311  4.7K  [R402-25]  73.53 51.82 90 bottom
R312  4.7K  [R402-25]  77.22 51.31 270 bottom
R328  4.7K  [R402-25]  79.12 45.47 270 bottom
R329  4.7K  [R402-25]  77.85 45.47 270 bottom
R330  4.7K  [R402-25]  76.71 45.47 270 bottom
R342  3.32K  [R402-25]  90.55 48.77 270 bottom
R344  1.5K  [R402-25]  90.68 51.44 0 bottom
R346  240  [R402-25]  91.57 48.77 270 bottom
R358  3.32K  [R402-25]  95.5 50.29 90 bottom
R360  3.32K  [R402-25]  96.65 50.29 90 bottom
R365  3.32K  [R402-25]  97.79 50.29 90 bottom
R371  100  [R402-25]  104.14 58.29 270 bottom
R372  100  [R402-25]  100.33 58.29 270 bottom
R382  3.32K  [R402-25]  109.22 63.63 270 bottom
R388  62  [R1206-40X70]  112.52 64.01 180 bottom
R401  NP  [R402-25]  37.59 23.88 0 bottom
R403  33  [R402-25]  108.58 96.39 0 bottom
R404  33  [R402-25]  108.58 95.25 0 bottom
R405  33  [R402-25]  108.58 93.85 0 bottom
R406  33  [R402-25]  108.58 92.71 0 bottom
R407  33  [R402-25]  108.58 91.31 0 bottom
R408  33  [R402-25]  108.58 90.04 0 bottom
R409  1K  [R402-25]  118.75 87.38 0 top
R410  10K  [R402-25]  106.05 88.77 0 bottom
R411  33  [R402-25]  108.58 88.77 0 bottom
R412  10K  [R402-25]  112.65 85.85 270 top
R426  100  [R402-25]  100.33 63.63 270 bottom
R428  2K  [R402-25]  35.56 15.24 180 top
R430  100K  [R402-25]  42.04 31.5 270 bottom
R431  274K  [R402-25]  40.26 26.8 0 bottom
R432  100K  [R402-25]  40.26 28.96 0 bottom
R433  0  [R402-25]  37.72 31.37 270 bottom
R435  33.2K  [R402-25]  106.68 63.63 270 bottom
R436  100  [R402-25]  109.22 58.29 90 bottom
R437  3.32K  [R402-25]  20.7 52.07 270 bottom
R438  100  [R402-25]  106.68 58.29 90 bottom
R439  100  [R402-25]  107.95 63.63 270 bottom
R440  10K  [R402-25]  106.68 60.96 270 bottom
R441  10K  [R402-25]  99.06 63.63 270 bottom
R443  10K  [R402-25]  96.52 86.87 270 top
R444  3.32K  [R402-25]  84.84 93.34 270 top
R445  0  [R201-6P6SPC]  61.09 77.6 180 top
R446  100K  [R402-25]  107.95 58.29 270 bottom
R447  NP  [R402-25]  54.61 93.6 90 top
R448  10K  [R402-25]  113.28 45.21 0 top
R449  1K  [R402-25]  114.05 52.2 90 top
R450  1K  [R402-25]  114.05 49.53 270 top
R600  28K  [R402-25]  38.86 47.88 270 top
R601  10K  [R402-25]  70.23 94.61 270 top
R602  10K  [R402-25]  40.26 56.77 270 bottom
R603  10K  [R402-25]  40.89 53.59 90 bottom
R604  NP-10K  [R402-25]  40.89 51.05 270 bottom
R605  100  [R402-25]  75.69 96.39 90 bottom
R606  10K  [R402-25]  75.06 94.49 180 bottom
R608  1K  [R402-25]  113.16 101.73 270 bottom
R609  10K  [R402-25]  110.87 101.73 270 bottom
R610  10K  [R402-25]  112.01 101.73 270 bottom
R611  10K  [R402-25]  107.95 100.97 90 bottom
R619  NP-2K  [R402-25]  109.22 99.95 270 bottom
R620  0  [R402-25]  111 108.58 0 bottom
R621  10  [R402-25]  108.84 110.11 270 top
R622  0.025  [R0612]  106.43 112.27 180 top
R623  24K  [R402-25]  119.89 103.5 0 top
R624  1  [R603-35X45]  103.12 109.98 270 top
R625  3.01 3/4W  [R1206-40X70]  125.09 114.17 90 bottom
R626  3.01 3/4W  [R1206-40X70]  121.41 114.17 90 bottom
R627  100  [R201-6P6SPC]  87.27 90.96 225 bottom
RJ16  10K.A  [JMP402-25]  100.2 82.04 180 bottom
RJ17  10K.A  [JMP402-25]  100.97 83.44 180 bottom
RJ18  10K.A  [JMP402-25]  83.57 81.28 180 bottom
RJ19  10K.A  [JMP402-25]  95.63 76.83 180 bottom
RJ20  10K.A  [JMP402-25]  99.19 76.83 180 bottom
RJ21  10K.A  [JMP402-25]  97.03 75.56 180 bottom
RJ22  10K.A  [JMP402-25]  93.47 75.56 180 bottom
RJ23  10K.A  [JMP402-25]  83.57 82.55 180 bottom
RJ24  10K.A  [JMP402-25]  83.57 85.09 180 bottom
RJ25  10K.A  [JMP402-25]  83.57 83.82 180 bottom
RJ26  0.A  [JMP402-25]  76.33 48.13 90 bottom
RJ27  3.32K.A  [JMP402-25]  104.14 61.85 270 bottom
RJ28  10K.A  [JMP402-25]  83.57 87.76 180 bottom
RJ29  10K.A  [JMP402-25]  100.97 86.36 180 bottom
RJ30  10K.A  [JMP402-25]  82.55 86.36 0 bottom
SW1  TDA06H0SB1R  [SW6-30X50-TDA]  77.85 83.82 180 top
SW2  SW DIP-2  [SW2-30X50-TDA]  28.07 37.72 90 top
TP1  TP  [TP-30RD13]  99.95 26.54 90 top
TP12  TP  [TP-30RD13]  37.72 35.56 270 top
TP16  SMT-TP  [TP1-70X135]  26.54 122.56 180 top
TP17  SMT-TP  [TP1-70X135]  108.33 41.66 0 top
TP18  TP  [TP-30RD13]  10.41 110.24 90 top
TP32  TP  [TP-30RD13]  43.43 62.99 0 top
TP36  TP  [TP-30RD13]  46.35 63.63 0 top
TP39  SMT-TP  [TP1-70X135]  4.06 33.15 0 top
TP40  TP  [TP-30RD13]  91.19 45.85 0 top
TP49  TP  [TP-30RD13]  100.08 54.86 270 top
TP51  TP  [TP-30RD13]  73.79 20.95 180 top
TP60  SMT-TP  [TP1-70X135]  128.65 113.67 0 top
TP63  SMT-TP  [TP1-70X135]  24.89 122.56 180 bottom
TP64  SMT-TP  [TP1-70X135]  4.57 14.86 180 bottom
TP65  SMT-TP  [TP1-70X135]  129.92 15.49 180 bottom
TP66  SMT-TP  [TP1-70X135]  109.6 70.61 180 bottom
TP67  TP  [TP-30RD13]  84.45 90.42 0 top
TP600  TP  [TP-30RD13]  72.77 37.21 180 top
U3  TPD1E05U06  [DPY-RDPADS]  29.46 113.92 135 top
U4  TPD1E05U06  [DPY-RDPADS]  31.24 113.92 45 top
U5  TPD1E05U06  [DPY-RDPADS]  39.62 113.92 135 top
U6  TPD1E05U06  [DPY-RDPADS]  41.4 113.92 45 top
U7  TPD1E05U06  [DPY-RDPADS]  32.51 112.01 135 top
U8  TPD1E05U06  [DPY-RDPADS]  34.29 112.01 45 top
U9  TPD1E05U06  [DPY-RDPADS]  36.58 112.01 135 top
U10  TPD1E05U06  [DPY-RDPADS]  38.35 112.01 45 top
U16  LM74610  [DGK8-14X70]  121.79 22.1 0 top
U17  TPD12S016RKTR  [RKT24]  47.37 113.54 270 top
U18  LM5141-Q1  [RGE24-11X28-4MM]  33.4 21.59 270 top
U22  24WC256  [SO8-25X75-295]  16.38 110.87 90 top
U23  MT41K512M16HA-125 AIT:A  [BGA6X16-P8-RE-PKG]  15.11 92.33 270 top
U26  PCA9306/PCA9306-Q1  [DCU8-10X50]  51.18 122.17 90 top
U27  X777AJGCBD  [J6ENTRY_DRA71X_ZDN_V4]  49.53 82.04 180 top
U29  MT41K512M16HA-125 AIT:A  [BGA6X16-P8-RE-PKG]  15.11 78.11 270 top
U31  MTFC32GAKAEDQ-AIT  [BGA100_1MM]  80.77 63.25 0 top
U35  TPS51200DRC  [DRC10-11X33]  11.81 46.99 180 top
U40  DP83TC811-Q1  [RND36-24X10]  94.87 52.7 0 top
U42  TPS61252  [DSG8-11X20]  71.75 26.29 0 top
U52  FT232RQ  [QFN32_5X5]  19.81 118.49 180 bottom
U54  SN74LVC1G125DCKR  [DCK-5]  72.52 59.82 0 bottom
U66  TPD2E001DRL-Q1  [DRL5-12X40]  111.76 90.81 270 bottom
U67  TPD2E001DRL-Q1  [DRL5-12X40]  111.76 93.34 270 bottom
U68  TPD2E001DRL-Q1  [DRL5-12X40]  111.76 95.89 270 bottom
U69  TPD2E001DRL-Q1  [DRL5-12X40]  111.76 88.27 270 bottom
U70  TPS22965DSG  [DSG8-11X20]  109.6 84.58 90 top
U76  NP-TPS3803-01-Q1  [DCK-5]  35.69 31.37 0 bottom
U77  DS90C189-Q1  [RTD64]  92.08 85.09 90 bottom
U78  TAS2505IR  [RGE24-11X28-4MM]  23.11 51.69 0 top
U79  TCAN1043D-Q1  [SO14-25X75]  104.14 60.96 0 top
U600  LP5912Q1.8DRVTQ1  [DRV6-12X30]  65.79 95.76 90 top
U601  TPS22965-Q1DSG  [DSG8-11X20]  71.75 34.04 270 top
U602  LP87523-Q1  [VQFNHR26]  39.62 52.32 90 top
U603  LP5907QMFX-1.8Q1  [DBV5-27X39]  65.66 102.62 180 top
U604  TLV7103318-Q1  [DSE6]  72.26 94.61 0 top
U605  TLV71318PQDBVRQ1  [DBV5-27X39]  72.52 102.62 180 top
U606  LP8860-Q1  [VFP0032B]  117.73 110.11 90 top
Y2  25MHz/10pF  [XTAL4-ABM11]  94.61 46.61 270 top
Y3  19.2MHz/10pF  [XTAL4-ABM11]  50.67 95.5 270 bottom

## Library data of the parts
C1-C3 C23 C624 C629 = CAP
C8 C24 C122 C129 C189 C212 C427 C435 C436 C541 C546 C547 C552 C556 C558-C560 C563 C565 C569 = CAP: Tolerance: X; User Part Number: X
C29 C30 C37 C38 C620-C623 C630 C632 C634 = CAP NP_0: Tolerance: X; User Part Number: X
C36 C43 C53 C554 = CAP NP_2: User Part Number: USERPART#; Tolerance: TOLERANCE
C39 C143 C144 C153 C154 C156 C163 C631 C635-C640 = CAP NP: Tolerance: X; User Part Number: X
C40 C276 C292 C375 C503 C506 C553 = CAP NP_3: User Part Number: USERPART#; Tolerance: TOLERANCE
C41 C48 C51 C54 C71 C73 C81 C83 C157 C160 C161 C267-C270 C442 C633 C641 C642 = CAP NP: User Part Number: USERPART#; Tolerance: TOLERANCE
C45 C78 = CAP NP_2: Tolerance: X; User Part Number: X
C56 C59 C64 = CAP NP_0: Tolerance: 20%; User Part Number: X; tolerance: 20%
C72 C220 C409 C410 C429 C507-C509 C511 C514 C518 C519 C521 C525 C566 C568 = CAP: User Part Number: USERPART#; Tolerance: TOLERANCE
C80 C82 C84 C91 C96 C272-C274 C293-C295 C297 C299 C311-C315 C319 C321 C325-C328 C332 C341 C347 C348 C351 C352 C354 C357 C361 C362 C364 C367 C368 C377 C386 C391 C392 C413-C415 C417-C425 = CAP_AM_0402_0.47uf_x7s_10v_20_X: Tolerance: +/-10%; User Part Number: USERPART#; tolerance: +/-10%
C89 C98 C108 C120 C194 C203 C204 C281 C307 C536 C537 C551 C605 C606 C610 C612 C613 = CAP_AM_0805_10uf_x7r_10v_10_X: Tolerance: X; User Part Number: X
C114 C370 C428 = CAP_AM_0402_0.47uf_x7s_10v_20_X: User Part Number: USERPART#; Tolerance: +/-10%; tolerance: +/-10%
C118 C284 C434 = CAP_AM_0402_1uF_X7S_10V_10%_X: User Part Number: USERPART#; Tolerance: 10%; tolerance: 10%
C119 C600 C603 = CAP_AM_0805_4.7uf_x7r_16v_10_X: Tolerance: X; User Part Number: X
C155 C158 C164 = CAP NP: Tolerance: TOLERANCE; User Part Number: USERPART#
C232 C233 = CAP NP: Tolerance: X; User Part Number: X; signal model: CAP_NP_C603-35X45_0.1UF
C275 = CAP .1 uF 10% 0603: User Part Number: USERPART#; Tolerance: TOLERANCE
C277 C282 C283 C285 C287 C288 C296 C342 C379 C390 C430-C432 = CAP_AM_0402_0.1uf_x7r_16v_10%_X: User Part Number: USERPART#; Tolerance: TOLERANCE
C278-C280 C298 C300 C304-C306 C308-C310 C318 C331 C333 C335-C338 C340 C345 C349 C356 C359 C369 C378 C382 C383 C416 = CAP_AM_0402_0.1uf_x7r_16v_10%_X: Tolerance: TOLERANCE; User Part Number: USERPART#
C286 C301 C302 C320 C322 C324 C329 C334 C343 C358 C372 C374 C388 C394 C395 C406-C408 C412 C426 = CAP_AM_0402_1uF_X7S_10V_10%_X: Tolerance: 10%; User Part Number: USERPART#; tolerance: 10%
C289 C303 C323 C344 C373 C380 C385 C393 C401-C403 = CAP_AM_0508_1uF_X7S_4V_20%_X: tolerance: 20%
C411 C437 = Cap 100nF Cermc 16V 10% 603_4: Tolerance: X; User Part Number: X
C433 C540 C542-C545 C557 C561 C562 C567 = Cap 100nF Cermc 16V 10% 603_4: User Part Number: USERPART#; Tolerance: TOLERANCE
C601 C602 C615 C616 = CAP_0805_22uF_X7R_6.3V_20%_X_SD: Tolerance: 20%; User Part Number: X; tolerance: 20%
C604 C618 = CAP_0402_0.1uf_x7r_16v_10%_X_SD: User Part Number: USERPART#; Tolerance: +/-10%; tolerance: +/-10%
C607 = CAP_0402_1uF_X7R_6.3V_10%_X_SD: Tolerance: 10%; User Part Number: X; tolerance: 10%
C608 = CAP_0402_220pf_x7r_50v_10%_X_SD: User Part Number: USERPART#; Tolerance: +/-10%; tolerance: +/-10%
C609 C614 = CAP_AM_0603_2.2uf_x7r_6.3v_10_X: Tolerance: X; User Part Number: X
C611 C617 = C_2.2uF/0402/6.3V_X5R_0402: Tolerance: X; User Part Number: X
C619 = CAP: Tolerance: TOLERANCE; User Part Number: USERPART#
C625-C628 = CAP NP_0: User Part Number: X; Tolerance: X
D5 = DIODE SCHOTTKY_0: Tolerance: TOLERANCE; User Part Number: USERPART#
D21 D22 = Diode_SMCJ15CA
D23 = DIODE SCHOTTKY_0: User Part Number: X; Tolerance: X
D24 = DIODE ZENER: Tolerance: TOLERANCE; User Part Number: USERPART#
D25 = PDS5100
D26 D27 = Diode_SMCJ15CA: User Part Number: X; Tolerance: X
DS1 = LED_RED_0: Tolerance: X; User Part Number: X
E1-E7 = EMIFIL_0805_0.47uF_2A_80dB27M_X: Tolerance: TOL; User Part Number: PART#
FL3 FL4 FL7 FL8 = DLW21SN900HQ2: User Part Number: PART#; Tolerance: TOL; signal model: DLW21SN900HQ2_EMI-36X15-DLW21-R
J1 = HEADER 2: Tolerance: X; User Part Number: X
J4 = HEADER 2
J7 = USBMINI_B_0
J14 = MIPI-QTH-030_1: User Part Number: PART#; Tolerance: TOL
J17 = Molex34826-0124: Tolerance: TOLERANCE; User Part Number: USERPART#
J24 = Molex_0436500400
J25 = FH41-40S-0.5SH_5
L1 = CHOKE HASH-IRON: Tolerance: TOLERANCE; User Part Number: USERPART#
L6 L34 = INDUCTOR IRON: Tolerance: X; User Part Number: X
L9 = INDUCTOR_3: Tolerance: X; User Part Number: X
L16 L17 L45 = FERRITE CHIP_0: Tolerance: X; User Part Number: X
L44 = CHOKE CM_AE2002: User Part Number: USERPART#; Tolerance: TOLERANCE; signal model: CHOKE_CM_AE2002_CHOKE4-AE2002_A
L600-L603 = IND_1008_0.47uH_6A_20%_X_SD: Tolerance: +/-20%; User Part Number: X; tolerance: +/-20%
L604 = INDUCTOR IRON: User Part Number: X; Tolerance: X
M1-M4 = MHP125-250
P1 = HDMI-RA-19_0: Tolerance: TOL; User Part Number: PART#
P9 = QSH-020-01-L-D-DP-A: Tolerance: TOL; User Part Number: PART#
P10 = molex-502774-0891: User Part Number: X; Tolerance: X
Q3 = MOSFET_CSD16406Q3_0: User Part Number: X; Tolerance: X
Q9 Q10 Q603 = BSZ042N06NS: User Part Number: X; Tolerance: X
Q12 Q600 Q602 = BSS138PS: User Part Number: X; Tolerance: X
R18 R23-R26 R29 R33 R36 R39 R51 R70 R104 R117 R118 R120 R128 R129 R140 R141 R143 R212 R215-R218 R221 R222 R232-R234 R262-R264 R292 R296 R307-R312 R328-R330 R342 R344 R346 R358 R360 R365 R371 R372 R382 R401 R426 R428 R430-R432 R435-R441 R443 R444 R446 R448 R605 R608-R611 = R: User Part Number: USERPART#; Tolerance: TOLERANCE
R22 R34 R35 R202 R213 R214 R219 R220 R433 R449 R450 R620 R621 R623 = R_2: User Part Number: USERPART#; Tolerance: TOLERANCE
R27 R28 R30-R32 R75 R97 R265 R266 R627 = R: Tolerance: TOLERANCE; User Part Number: USERPART#
R52 R55 R56 R64 R76 = R_0: User Part Number: USERPART#; Tolerance: TOLERANCE
R66 R99 R445 = R: Tolerance: TOLERANCE; User Part Number: USERPART#; signal model: R_R201-6P6SPC_0
R71 R236 R447 R606 = RES_0402_10k_1.0%_0.063W_X: User Part Number: USERPART#; Tolerance: 1.0%; tolerance: 1.0%
R83-R96 R276-R288 = RES_0402_49.9_1%_0.063W_X: User Part Number: USERPART#; Tolerance: 1.0%; tolerance: 1.0%
R101 = R0402-22: Tolerance: TOLERANCE; User Part Number: USERPART#; signal model: R201-6P6SPC_0a
R152 R388 = R: Tolerance: X; User Part Number: X
R225 R625 R626 = R_2: Tolerance: X; User Part Number: X
R226-R231 R268-R273 R289 R291 R295 R300 R403-R412 R602 = RESISTOR: User Part Number: USERPART#; Tolerance: TOLERANCE
R235 R240 R241 R243 R244 R247 R248 R250 R251 R254 R255 R258 R259 = R_1: User Part Number: USERPART#; Tolerance: TOLERANCE
R245 R246 R249 R619 = RESISTOR_0: User Part Number: USERPART#; Tolerance: TOLERANCE
R299 = RESISTOR: User Part Number: USERPART#; Tolerance: TOLERANCE; signal model: RESISTOR_R402-25_0
R600 = R_10K_0402_1%_Multi: User Part Number: USERPART#; Tolerance: TOLERANCE
R601 R603 R604 = RESISTOR: Tolerance: TOLERANCE; User Part Number: USERPART#
R622 = RESISTOR: Tolerance: X; User Part Number: X
R624 = R_2: User Part Number: X; Tolerance: X
RJ16-RJ30 = RJUMP3: Tolerance: TOLERANCE; User Part Number: USERPART#
SW1 = SW DIP-6/SM_0: Tolerance: X; User Part Number: X
SW2 = SW DIP-2_0: User Part Number: X; Tolerance: X
TP1 TP12 TP18 TP32 TP36 TP40 TP51 TP67 TP600 = TP-30RD13: Tolerance: TOLERANCE; User Part Number: USERPART#
TP16 TP17 TP39 TP60 TP63-TP66 = SMT-TP
TP49 = TESTPOINT: Tolerance: TOLERANCE; User Part Number: USERPART#
U3-U10 = TPD1E05U06: Tolerance: X; User Part Number: X
U16 = LM74610: User Part Number: X; Tolerance: X
U17 = TPD12S016RKTR_QFN24_3: Tolerance: X; User Part Number: X
U18 = LM5141-Q1
U22 = 24WC256: User Part Number: X; Tolerance: X
U23 U29 = IC_MT41K128M16JT_DDR3L_96FBGA_X
U26 = PCA9306
U27 = IC_J6Entry_17mm_538BGA_v1.2
U31 = MTFC32GAKAEDQ-AIT: Tolerance: TOL; User Part Number: PART#
U35 = IC_TPS51200DRC_SON10_X: Tolerance: X; User Part Number: X
U40 = DP83TC811-Q1
U42 = TPS61252: User Part Number: X; Tolerance: X
U52 = FT232RQ_7: User Part Number: PART#; Tolerance: TOL
U54 = SN74LVC1G125_0: Tolerance: TOL; User Part Number: PART#
U66-U69 = TPDE0001RSE_0: Tolerance: TOL; User Part Number: PART#
U70 = TPS22965DSG: User Part Number: X; Tolerance: X
U76 = TPS3803-01-Q1: Tolerance: TOL; User Part Number: PART#
U77 = DS90C189-Q1
U78 = TAS2505IR
U79 = TCAN1043D-Q1: Tolerance: X; User Part Number: X
U600 = LP5912-Q1: User Part Number: X; Tolerance: X
U601 = IC_TPS22965Q1DSG_SON8_X: User Part Number: X; Tolerance: X
U602 = LP87523-Q1: User Part Number: PART#; Tolerance: TOL
U603 = LP5907-Q1: Tolerance: X; User Part Number: X
U604 = TLV7103318-Q1
U605 = TLV713P-Q1: Tolerance: X; User Part Number: X
U606 = LP8860-Q1: User Part Number: X; Tolerance: X
Y2 Y3 = CRYSTAL 4-PIN_0

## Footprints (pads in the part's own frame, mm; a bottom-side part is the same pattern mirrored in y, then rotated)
BGA6X16-P8-RE-PKG
  round 0.351 smd: A1(-3.2,6) A2(-2.4,6) A3(-1.6,6) A7(1.6,6) A8(2.4,6) A9(3.2,6) B1(-3.2,5.2) B2(-2.4,5.2) B3(-1.6,5.2) B7(1.6,5.2) B8(2.4,5.2) B9(3.2,5.2) C1(-3.2,4.4) C2(-2.4,4.4) C3(-1.6,4.4) C7(1.6,4.4) C8(2.4,4.4) C9(3.2,4.4) D1(-3.2,3.6) D2(-2.4,3.6) D3(-1.6,3.6) D7(1.6,3.6) D8(2.4,3.6) D9(3.2,3.6) E1(-3.2,2.8) E2(-2.4,2.8) E3(-1.6,2.8) E7(1.6,2.8) E8(2.4,2.8) E9(3.2,2.8) F1(-3.2,2) F2(-2.4,2) F3(-1.6,2) F7(1.6,2) F8(2.4,2) F9(3.2,2) G1(-3.2,1.2) G2(-2.4,1.2) G3(-1.6,1.2) G7(1.6,1.2) G8(2.4,1.2) G9(3.2,1.2) H1(-3.2,0.4) H2(-2.4,0.4) H3(-1.6,0.4) H7(1.6,0.4) H8(2.4,0.4) H9(3.2,0.4) J1(-3.2,-0.4) J2(-2.4,-0.4) J3(-1.6,-0.4) J7(1.6,-0.4) J8(2.4,-0.4) J9(3.2,-0.4) K1(-3.2,-1.2) K2(-2.4,-1.2) K3(-1.6,-1.2) K7(1.6,-1.2) K8(2.4,-1.2) K9(3.2,-1.2) L1(-3.2,-2) L2(-2.4,-2) L3(-1.6,-2) L7(1.6,-2) L8(2.4,-2) L9(3.2,-2) M1(-3.2,-2.8) M2(-2.4,-2.8) M3(-1.6,-2.8) M7(1.6,-2.8) M8(2.4,-2.8) M9(3.2,-2.8) N1(-3.2,-3.6) N2(-2.4,-3.6) N3(-1.6,-3.6) N7(1.6,-3.6) N8(2.4,-3.6) N9(3.2,-3.6) P1(-3.2,-4.4) P2(-2.4,-4.4) P3(-1.6,-4.4) P7(1.6,-4.4) P8(2.4,-4.4) P9(3.2,-4.4) R1(-3.2,-5.2) R2(-2.4,-5.2) R3(-1.6,-5.2) R7(1.6,-5.2) R8(2.4,-5.2) R9(3.2,-5.2) T1(-3.2,-6) T2(-2.4,-6) T3(-1.6,-6) T7(1.6,-6) T8(2.4,-6) T9(3.2,-6)
BGA100_1MM
  round 0.508 smd: A1(-4.503,8.006) A2(-3.503,8.006) A9(3.503,8.006) A10(4.503,8.006) B1(-4.503,7.005) B10(4.503,7.005) D2(-3.503,5.004) D3(-2.502,5.004) D4(-1.501,5.004) D5(-0.5,5.004) D6(0.5,5.004) D7(1.501,5.004) D8(2.502,5.004) D9(3.503,5.004) E2(-3.503,4.003) E3(-2.502,4.003) E4(-1.501,4.003) E5(-0.5,4.003) E6(0.5,4.003) E7(1.501,4.003) E8(2.502,4.003) E9(3.503,4.003) F2(-3.503,3.002) F3(-2.502,3.002) F4(-1.501,3.002) F5(-0.5,3.002) F6(0.5,3.002) F7(1.501,3.002) F8(2.502,3.002) F9(3.503,3.002) G2(-3.503,2.002) G3(-2.502,2.002) G4(-1.501,2.002) G5(-0.5,2.002) G6(0.5,2.002) G7(1.501,2.002) G8(2.502,2.002) G9(3.503,2.002) H2(-3.503,1.001) H3(-2.502,1.001) H4(-1.501,1.001) H5(-0.5,1.001) H6(0.5,1.001) H7(1.501,1.001) H8(2.502,1.001) H9(3.503,1.001) J2(-3.503,0) J3(-2.502,0) J4(-1.501,0) J5(-0.5,0) J6(0.5,0) J7(1.501,0) J8(2.502,0) J9(3.503,0) K2(-3.503,-1.001) K3(-2.502,-1.001) K4(-1.501,-1.001) K5(-0.5,-1.001) K6(0.5,-1.001) K7(1.501,-1.001) K8(2.502,-1.001) K9(3.503,-1.001) L2(-3.503,-2.002) L3(-2.502,-2.002) L4(-1.501,-2.002) L5(-0.5,-2.002) L6(0.5,-2.002) L7(1.501,-2.002) L8(2.502,-2.002) L9(3.503,-2.002) M2(-3.503,-3.002) M3(-2.502,-3.002) M4(-1.501,-3.002) M5(-0.5,-3.002) M6(0.5,-3.002) M7(1.501,-3.002) M8(2.502,-3.002) M9(3.503,-3.002) N2(-3.503,-4.003) N3(-2.502,-4.003) N4(-1.501,-4.003) N5(-0.5,-4.003) N6(0.5,-4.003) N7(1.501,-4.003) N8(2.502,-4.003) N9(3.503,-4.003) P2(-3.503,-5.004) P3(-2.502,-5.004) P4(-1.501,-5.004) P5(-0.5,-5.004) P6(0.5,-5.004) P7(1.501,-5.004) P8(2.502,-5.004) P9(3.503,-5.004) T1(-4.503,-7.005) T10(4.503,-7.005) U1(-4.503,-8.006) U2(-3.503,-8.006) U9(3.503,-8.006) U10(4.503,-8.006)
C402-25
  round 0.635 smd: 1(-0.508,0) 2(0.508,0)
C402-25RD
  round 0.635 smd: 1(-0.508,0) 2(0.508,0)
C603-35X45
  oval 0.889x1.143 smd: 1(-0.762,0) 2(0.762,0)
C805-35X60
  oval 0.889x1.524 smd: 1(-0.965,0) 2(0.965,0)
C1206-40X70
  oval 1.016x1.778 smd: 1(-1.524,0) 2(1.524,0)
C1210-70X102
  rect 1.778x3.048 smd: 1(-1.803,0) 2(1.803,0)
C2220-60X230
  rect 1.524x5.842 smd: 1(-2.819,0) 2(2.819,0)
CAP300X630UP
  rect 2.032x2.032 hole 1.049: 1(-7.62,0)
  round 2.032 hole 1.049: 2(0,0)
CAP-F-8383A
  rect 1.524x4.445 smd: 1(0,3.099) 2(0,-3.099)
CHOKE4-AE2002
  rect 1.27x0.762 smd: 1(-2.349,0.699) 2(-2.349,-0.699) 3(2.349,-0.699) 4(2.349,0.699)
COIL-XAL60
  rect 1.27x5.283 smd: 1(-2.032,0) 2(2.032,0)
CON2R-150
  rect 2.54x2.54 hole 1.397: 1(0,0)
  round 2.54 hole 1.397: 2(3.81,0)
DBV5-27X39
  rect 0.686x0.991 smd: 1(-0.95,-1.321) 2(0,-1.321) 3(0.95,-1.321) 4(0.95,1.321) 5(-0.95,1.321)
DCK-5
  rect 0.46x0.66 smd: 1(-0.65,-0.991) 2(0,-0.991) 3(0.65,-0.991) 4(0.65,0.991) 5(-0.65,0.991)
DCU8-10X50
  oval 0.254x1.27 smd: 1(-0.747,-1.499) 2(-0.249,-1.499) 3(0.249,-1.499) 4(0.747,-1.499) 5(0.747,1.499) 6(0.249,1.499) 7(-0.249,1.499) 8(-0.747,1.499)
DGK8-14X70
  oval 0.356x1.778 smd: 1(-0.975,-2.225) 2(-0.325,-2.225) 3(0.325,-2.225) 4(0.975,-2.225) 5(0.975,2.223) 6(0.325,2.223) 7(-0.325,2.223) 8(-0.975,2.223)
DIODE-POWERDI5
  rect 1.143x1.143 smd: ANODE1(-2.87,0.914) ANODE2(-2.87,-0.914)
  rect 4.877x3.353 smd: CATHODE(0.991,0)
DPY-RDPADS
  oval 0.61x0.508 smd: 1(-0.495,0) 2(0.495,0)
DRC10-11X33
  rect 0.305x0.762 smd: 1(-1.001,-1.473) 2(-0.5,-1.473) 3(0,-1.473) 4(0.5,-1.473) 5(1.001,-1.473) 6(1.001,1.473) 7(0.5,1.473) 8(0,1.473) 9(-0.5,1.473) 10(-1.001,1.473)
  custom 0.406x0.406 smd: 11(0,0)
DRL5-12X40
  rect 0.305x1.016 smd: 1(-0.5,-0.813) 2(0,-0.813) 3(0.5,-0.813) 4(0.5,0.813) 5(-0.5,0.813)
DRV6-12X30
  rect 0.305x0.762 smd: 1(-0.65,-1.016) 2(0,-1.016) 3(0.65,-1.016) 4(0.65,1.016) 5(0,1.016) 6(-0.65,1.016)
  rect 1.397x0.889 smd: 7(0,0)
DSE6
  rect 0.305x1.143 smd: 1(-0.5,-0.597)
  rect 0.305x1.016 smd: 2(0,-0.66) 3(0.5,-0.66) 4(0.5,0.66) 5(0,0.66) 6(-0.5,0.66)
DSG8-11X20
  rect 0.279x0.508 smd: 1(-0.75,-0.965) 2(-0.25,-0.965) 3(0.25,-0.965) 4(0.75,-0.965) 5(0.75,0.965) 6(0.25,0.965) 7(-0.25,0.965) 8(-0.75,0.965)
  rect 1.6x0.889 smd: 9(0,0)
EMI-36X15-DLW21-RDPADS
  oval 0.914x0.381 smd: 1(-0.838,0.406) 2(0.838,0.406) 3(0.838,-0.406) 4(-0.838,-0.406)
EMI-NFM21P
  rect 0.889x0.813 smd: 1(-1.118,0) 3(1.118,0)
  rect 0.508x2.007 smd: 2(0,0)
FH41-40S-SH
  rect 0.3x0.66 smd: 1(-9.754,3.048) 2(-9.253,3.048) 3(-8.753,3.048) 4(-8.252,3.048) 5(-7.752,3.048) 6(-7.254,3.048) 7(-6.754,3.048) 8(-6.253,3.048) 9(-5.753,3.048) 10(-5.253,3.048) 11(-4.755,3.048) 12(-4.255,3.048) 13(-3.754,3.048) 14(-3.254,3.048) 15(-2.753,3.048) 16(-2.256,3.048) 17(-1.755,3.048) 18(-1.255,3.048) 19(-0.754,3.048) 20(-0.254,3.048) 21(0.246,3.048) 22(0.747,3.048) 23(1.247,3.048) 24(1.748,3.048) 25(2.248,3.048) 26(2.748,3.048) 27(3.249,3.048) 28(3.749,3.048) 29(4.249,3.048) 30(4.75,3.048) 31(5.25,3.048) 32(5.751,3.048) 33(6.251,3.048) 34(6.751,3.048) 35(7.252,3.048) 36(7.752,3.048) 37(8.252,3.048) 38(8.753,3.048) 39(9.253,3.048) 40(9.754,3.048)
  rect 0.3x1.194 smd: 41(-8.763,-2.616) 42(-6.261,-2.616) 43(-3.759,-2.616) 44(-1.257,-2.616) 45(1.245,-2.616) 46(3.747,-2.616) 47(6.248,-2.616) 48(8.75,-2.616)
  rect 0.406x1.524 smd: 49(-10.998,-2.184) 50(10.998,-2.184)
HDMI-SMT-W-FLANGE-RDPADS
  oval 0.279x1.905 smd: 1(4.75,0) 2(4.249,0) 3(3.749,0) 4(3.249,0) 5(2.748,0) 6(2.248,0) 7(1.748,0) 8(1.247,0) 9(0.747,0) 10(0.246,0) 11(-0.254,0) 12(-0.754,0) 13(-1.255,0) 14(-1.755,0) 15(-2.256,0) 16(-2.756,0) 17(-3.256,0) 18(-3.757,0) 19(-4.257,0)
  round 2.032 hole 1.295: MTG1(-7.239,-1.001) MTG2(7.239,-1.001) MTG3(-7.849,-5.9) MTG4(7.849,-5.9)
IND2-7030D
  rect 2.032x3.81 smd: 1(-2.921,0) 2(2.921,0)
IND2520-40X80
  rect 1.016x2.032 smd: 1(-1.118,0) 2(1.118,0)
IND-IHLP-COMBO
  custom 0.724x0.724 smd: 1(-3.607,0) 2(3.607,0)
J6ENTRY_DRA71X_ZDN_V4
  round 0.3 smd: A1(-7.8,7.8) A2(-7.15,7.8) A3(-6.5,7.8) A4(-5.85,7.8) A5(-5.2,7.8) A6(-4.55,7.8) A7(-3.9,7.8) A8(-3.25,7.8) A9(-2.6,7.8) A10(-1.95,7.8) A11(-1.3,7.8) A12(-0.65,7.8) A13(0,7.8) A14(0.65,7.8) A15(1.3,7.8) A16(1.95,7.8) A17(2.6,7.8) A18(3.25,7.8) A19(3.9,7.8) A20(4.55,7.8) A21(5.2,7.8) A22(5.85,7.8) A23(6.5,7.8) A24(7.15,7.8) A25(7.8,7.8) AA1(-7.8,-5.2) AA2(-7.15,-5.2) AA3(-6.5,-5.2) AA4(-5.852,-5.202) AA5(-5.202,-5.202) AA6(-4.552,-5.202) AA7(-3.9,-5.2) AA8(-3.251,-5.202) AA9(-2.6,-5.2) AA10(-1.95,-5.2) AA11(-1.3,-5.202) AA12(-0.65,-5.2) AA13(0,-5.2) AA15(1.3,-5.2) AA16(1.95,-5.2) AA18(3.25,-5.2) AA19(3.9,-5.2) AA20(4.552,-5.202) AA21(5.202,-5.202) AA23(6.502,-5.202) AA24(7.15,-5.2) AA25(7.8,-5.2) AB1(-7.8,-5.85) AB2(-7.153,-5.852) AB6(-4.55,-5.85) AB7(-3.9,-5.85) AB8(-3.251,-5.852) AB9(-2.6,-5.85) AB10(-1.95,-5.85) AB11(-1.3,-5.852) AB12(-0.65,-5.852) AB15(1.3,-5.85) AB16(1.95,-5.85) AB18(3.25,-5.85) AB19(3.9,-5.85) AB23(6.502,-5.852) AB24(7.15,-5.85) AB25(7.8,-5.85) AC1(-7.8,-6.5) AC2(-7.15,-6.5) AC3(-6.5,-6.5) AC4(-5.852,-6.502) AC5(-5.2,-6.5) AC6(-4.55,-6.5) AC8(-3.251,-6.502) AC10(-1.95,-6.5) AC11(-1.3,-6.502) AC13(0,-6.502) AC15(1.3,-6.5) AC16(1.95,-6.5) AC18(3.25,-6.5) AC19(3.901,-6.502) AC20(4.55,-6.5) AC21(5.2,-6.5) AC22(5.852,-6.502) AC23(6.5,-6.5) AC24(7.15,-6.5) AC25(7.8,-6.5) AD1(-7.8,-7.15) AD2(-7.153,-7.153) AD3(-6.5,-7.15) AD4(-5.85,-7.15) AD6(-4.552,-7.153) AD7(-3.9,-7.15) AD9(-2.601,-7.153) AD10(-1.95,-7.15) AD12(-0.65,-7.153) AD13(0,-7.15) AD15(1.3,-7.15) AD16(1.95,-7.15) AD17(2.6,-7.15) AD18(3.25,-7.15) AD19(3.9,-7.15) AD20(4.55,-7.15) AD21(5.2,-7.15) AD22(5.85,-7.15) AD23(6.5,-7.15) AD24(7.15,-7.15) AD25(7.8,-7.15) AE1(-7.8,-7.8) AE2(-7.15,-7.8) AE3(-6.5,-7.8) AE5(-5.2,-7.8) AE6(-4.55,-7.8) AE8(-3.25,-7.8) AE9(-2.6,-7.8) AE11(-1.3,-7.8) AE12(-0.65,-7.8) AE14(0.65,-7.8) AE15(1.3,-7.8) AE16(1.95,-7.8) AE17(2.6,-7.8) AE18(3.25,-7.8) AE19(3.9,-7.8) AE20(4.55,-7.8) AE21(5.2,-7.8) AE22(5.85,-7.8) AE23(6.5,-7.8) AE24(7.15,-7.8) AE25(7.8,-7.8) B1(-7.8,7.15) B2(-7.15,7.15) B3(-6.5,7.15) B4(-5.85,7.15) B5(-5.2,7.15) B6(-4.55,7.15) B7(-3.9,7.15) B8(-3.25,7.15) B9(-2.6,7.15) B10(-1.95,7.15) B11(-1.3,7.15) B12(-0.65,7.15) B13(0,7.15) B14(0.65,7.15) B15(1.3,7.15) B16(1.95,7.15) B17(2.6,7.15) B18(3.25,7.15) B19(3.9,7.15) B20(4.55,7.15) B21(5.2,7.15) B22(5.85,7.15) B23(6.5,7.15) B24(7.15,7.15) B25(7.8,7.15) C1(-7.8,6.5) C2(-7.15,6.5) C3(-6.5,6.5) C4(-5.852,6.502) C5(-5.2,6.5) C6(-4.55,6.5) C7(-3.901,6.502) C8(-3.25,6.5) C10(-1.95,6.5) C11(-1.3,6.5) C13(0,6.5) C14(0.65,6.5) C16(1.95,6.5) C17(2.6,6.5) C19(3.9,6.5) C20(4.55,6.5) C21(5.202,6.502) C22(5.852,6.502) C23(6.5,6.5) C24(7.15,6.5) C25(7.8,6.5) D1(-7.8,5.85) D2(-7.15,5.85) D3(-6.502,5.852) D6(-4.55,5.85) D7(-3.9,5.85) D8(-3.25,5.85) D10(-1.95,5.85) D11(-1.3,5.85) D13(0,5.85) D14(0.65,5.85) D16(1.95,5.85) D17(2.6,5.85) D19(3.9,5.85) D20(4.55,5.85) D23(6.502,5.852) D24(7.15,5.85) D25(7.8,5.85) E1(-7.8,5.2) E2(-7.15,5.2) E7(-3.9,5.2) E8(-3.25,5.2) E10(-1.95,5.2) E11(-1.3,5.2) E13(0,5.2) E14(0.65,5.2) E16(1.95,5.2) E17(2.6,5.2) E19(3.9,5.2) E20(4.552,5.202) E24(7.15,5.2) E25(7.8,5.2) F1(-7.8,4.55) F2(-7.15,4.55) F3(-6.5,4.55) F6(-4.55,4.55) F7(-3.9,4.55) F8(-3.25,4.55) F10(-1.95,4.55) F11(-1.3,4.552) F13(0,4.55) F14(0.65,4.55) F16(1.95,4.55) F17(2.6,4.55) F19(3.9,4.55) F20(4.55,4.55) F23(6.5,4.55) F24(7.15,4.55) F25(7.8,4.55) G1(-7.8,3.9) G2(-7.15,3.9) G3(-6.5,3.9) G4(-5.85,3.9) G5(-5.2,3.9) G6(-4.55,3.9) G7(-3.901,3.901) G8(-3.25,3.9) G9(-2.601,3.901) G10(-1.95,3.9) G11(-1.3,3.9) G12(-0.65,3.901) G13(0,3.9) G14(0.65,3.9) G15(1.3,3.901) G16(1.95,3.9) G17(2.6,3.9) G18(3.251,3.901) G19(3.901,3.901) G20(4.55,3.9) G21(5.2,3.9) G22(5.85,3.9) G23(6.502,3.901) G24(7.15,3.9) G25(7.8,3.9) H1(-7.8,3.25) H2(-7.15,3.25) H3(-6.502,3.251) H4(-5.852,3.251) H5(-5.202,3.251) H6(-4.552,3.251) H7(-3.901,3.251) H8(-3.25,3.25) H9(-2.6,3.25) H10(-1.95,3.25) H11(-1.3,3.25) H12(-0.65,3.25) H13(0,3.25) H14(0.65,3.25) H15(1.3,3.25) H16(1.95,3.25) H17(2.6,3.25) H18(3.25,3.25) H19(3.9,3.25) H20(4.55,3.25) H21(5.2,3.25) H22(5.85,3.25) H23(6.5,3.25) H24(7.15,3.25) H25(7.8,3.25) J1(-7.8,2.6) J2(-7.15,2.6) J7(-3.9,2.6) J8(-3.25,2.6) J9(-2.6,2.6) J10(-1.95,2.6) J11(-1.3,2.6) J12(-0.65,2.6) J13(0,2.6) J14(0.65,2.6) J15(1.3,2.6) J16(1.95,2.6) J17(2.6,2.6) J18(3.25,2.6) J19(3.901,2.601) J20(4.552,2.601) J24(7.15,2.6) J25(7.8,2.6) K1(-7.8,1.95) K2(-7.15,1.95) K3(-6.5,1.95) K4(-5.85,1.95) K5(-5.2,1.95) K6(-4.55,1.95) K7(-3.9,1.95) K8(-3.25,1.95) K9(-2.6,1.95) K10(-1.951,1.951) K11(-1.3,1.95) K12(-0.65,1.95) K13(0,1.951) K14(0.65,1.95) K15(1.3,1.95) K16(1.951,1.951) K17(2.6,1.95) K18(3.25,1.95) K19(3.9,1.95) K20(4.55,1.95) K21(5.2,1.95) K22(5.85,1.95) K23(6.5,1.95) K24(7.15,1.95) K25(7.8,1.95) L1(-7.8,1.3) L2(-7.15,1.3) L3(-6.502,1.3) L4(-5.852,1.3) L5(-5.202,1.3) L6(-4.552,1.3) L7(-3.901,1.3) L8(-3.25,1.3) L9(-2.6,1.3) L10(-1.951,1.3) L11(-1.3,1.3) L12(-0.65,1.3) L13(0,1.3) L14(0.65,1.3) L15(1.3,1.3) L16(1.951,1.3) L17(2.6,1.3) L18(3.25,1.3) L19(3.9,1.3) L20(4.55,1.3) L21(5.2,1.3) L22(5.85,1.3) L23(6.5,1.3) L24(7.15,1.3) L25(7.8,1.3) M1(-7.8,0.65) M2(-7.15,0.65) M7(-3.9,0.65) M8(-3.25,0.65) M9(-2.6,0.65) M10(-1.95,0.65) M11(-1.3,0.65) M12(-0.65,0.65) M13(0,0.65) M14(0.65,0.65) M15(1.3,0.65) M16(1.95,0.65) M17(2.6,0.65) M18(3.25,0.65) M19(3.901,0.65) M20(4.552,0.65) M24(7.15,0.65) M25(7.8,0.65) N1(-7.8,0) N2(-7.15,0) N3(-6.5,0) N4(-5.85,0) N5(-5.2,0) N6(-4.55,0) N7(-3.9,0) N8(-3.25,0) N9(-2.6,0) N10(-1.95,0) N11(-1.3,0) N12(-0.65,0) N13(0,0) N14(0.65,0) N15(1.3,0) N16(1.95,0) N17(2.6,0) N18(3.25,0) N19(3.9,0) N20(4.55,0) N21(5.2,0) N22(5.85,0) N23(6.5,0) N24(7.15,0) N25(7.8,0) P1(-7.8,-0.65) P2(-7.15,-0.65) P3(-6.502,-0.65) P4(-5.852,-0.65) P5(-5.202,-0.65) P7(-3.901,-0.65) P8(-3.25,-0.65) P9(-2.6,-0.65) P10(-1.95,-0.65) P11(-1.3,-0.65) P12(-0.65,-0.65) P13(0,-0.65) P14(0.65,-0.65) P15(1.3,-0.65) P16(1.95,-0.65) P17(2.6,-0.65) P18(3.25,-0.65) P19(3.9,-0.65) P20(4.55,-0.65) P21(5.2,-0.65) P22(5.85,-0.65) P23(6.5,-0.65) P24(7.15,-0.65) P25(7.8,-0.65) R1(-7.8,-1.3) R2(-7.15,-1.3) R7(-3.9,-1.3) R8(-3.25,-1.3) R9(-2.6,-1.3) R10(-1.951,-1.3) R11(-1.3,-1.3) R12(-0.65,-1.3) R13(0,-1.3) R14(0.65,-1.3) R15(1.3,-1.3) R16(1.951,-1.3) R17(2.6,-1.3) R18(3.25,-1.3) R19(3.901,-1.3) R20(4.552,-1.3) R24(7.15,-1.3) R25(7.8,-1.3) T1(-7.8,-1.95) T2(-7.15,-1.95) T3(-6.5,-1.95) T4(-5.85,-1.95) T5(-5.2,-1.95) T6(-4.55,-1.95) T7(-3.9,-1.95) T8(-3.25,-1.95) T9(-2.6,-1.95) T10(-1.951,-1.951) T11(-1.3,-1.95) T12(-0.65,-1.95) T13(0,-1.951) T14(0.65,-1.95) T15(1.3,-1.95) T16(1.951,-1.951) T17(2.6,-1.95) T18(3.25,-1.95) T19(3.9,-1.95) T20(4.55,-1.95) T21(5.2,-1.95) T22(5.85,-1.95) T23(6.5,-1.95) T24(7.15,-1.95) T25(7.8,-1.95) U1(-7.8,-2.6) U2(-7.15,-2.6) U3(-6.502,-2.601) U4(-5.852,-2.601) U5(-5.202,-2.601) U6(-4.552,-2.601) U7(-3.901,-2.601) U8(-3.25,-2.6) U9(-2.601,-2.601) U10(-1.95,-2.6) U11(-1.3,-2.6) U12(-0.65,-2.6) U13(0,-2.6) U14(0.65,-2.6) U15(1.3,-2.6) U16(1.95,-2.6) U17(2.6,-2.6) U18(3.25,-2.6) U19(3.9,-2.6) U20(4.55,-2.6) U21(5.2,-2.6) U22(5.85,-2.6) U23(6.5,-2.6) U24(7.15,-2.6) U25(7.8,-2.6) V1(-7.8,-3.25) V2(-7.15,-3.25) V3(-6.5,-3.25) V4(-5.85,-3.25) V5(-5.2,-3.25) V7(-3.9,-3.25) V8(-3.25,-3.25) V9(-2.6,-3.25) V10(-1.95,-3.25) V11(-1.3,-3.25) V12(-0.65,-3.25) V13(0,-3.25) V14(0.65,-3.25) V15(1.3,-3.25) V16(1.95,-3.25) V17(2.6,-3.25) V18(3.25,-3.25) V19(3.901,-3.251) V20(4.552,-3.251) V24(7.15,-3.25) V25(7.8,-3.25) W1(-7.8,-3.9) W2(-7.15,-3.9) W7(-3.901,-3.901) W8(-3.251,-3.901) W9(-2.601,-3.901) W10(-1.95,-3.9) W11(-1.3,-3.901) W12(-0.65,-3.9) W13(0,-3.9) W14(0.65,-3.901) W15(1.3,-3.9) W16(1.95,-3.9) W17(2.601,-3.901) W18(3.25,-3.9) W19(3.901,-3.901) W20(4.55,-3.9) W21(5.2,-3.9) W22(5.85,-3.9) W23(6.5,-3.9) W24(7.15,-3.9) W25(7.8,-3.9) Y1(-7.8,-4.55) Y2(-7.15,-4.55) Y3(-6.5,-4.55) Y4(-5.85,-4.55) Y5(-5.202,-4.552) Y6(-4.55,-4.55) Y7(-3.9,-4.55) Y8(-3.251,-4.552) Y9(-2.601,-4.552) Y10(-1.95,-4.55) Y11(-1.3,-4.552) Y12(-0.65,-4.55) Y13(0,-4.55) Y14(0.65,-4.552) Y15(1.3,-4.55) Y16(1.95,-4.55) Y17(2.601,-4.552) Y18(3.25,-4.55) Y19(3.9,-4.55) Y20(4.55,-4.55) Y21(5.202,-4.552) Y23(6.5,-4.55) Y24(7.15,-4.55) Y25(7.8,-4.55)
